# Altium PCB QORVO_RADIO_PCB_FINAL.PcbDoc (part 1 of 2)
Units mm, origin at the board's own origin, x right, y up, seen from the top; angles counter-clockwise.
Board outline 125 x 75 mm, 6 copper layers (Top Layer (RF), Int1 (GND), Int2 (5V+3.3V), Int3 (Controls), Int4 (GND), Bottom Layer (RF)), stack 1.538 mm thick; 307 components, 160 nets, 820 pads, 887 vias.
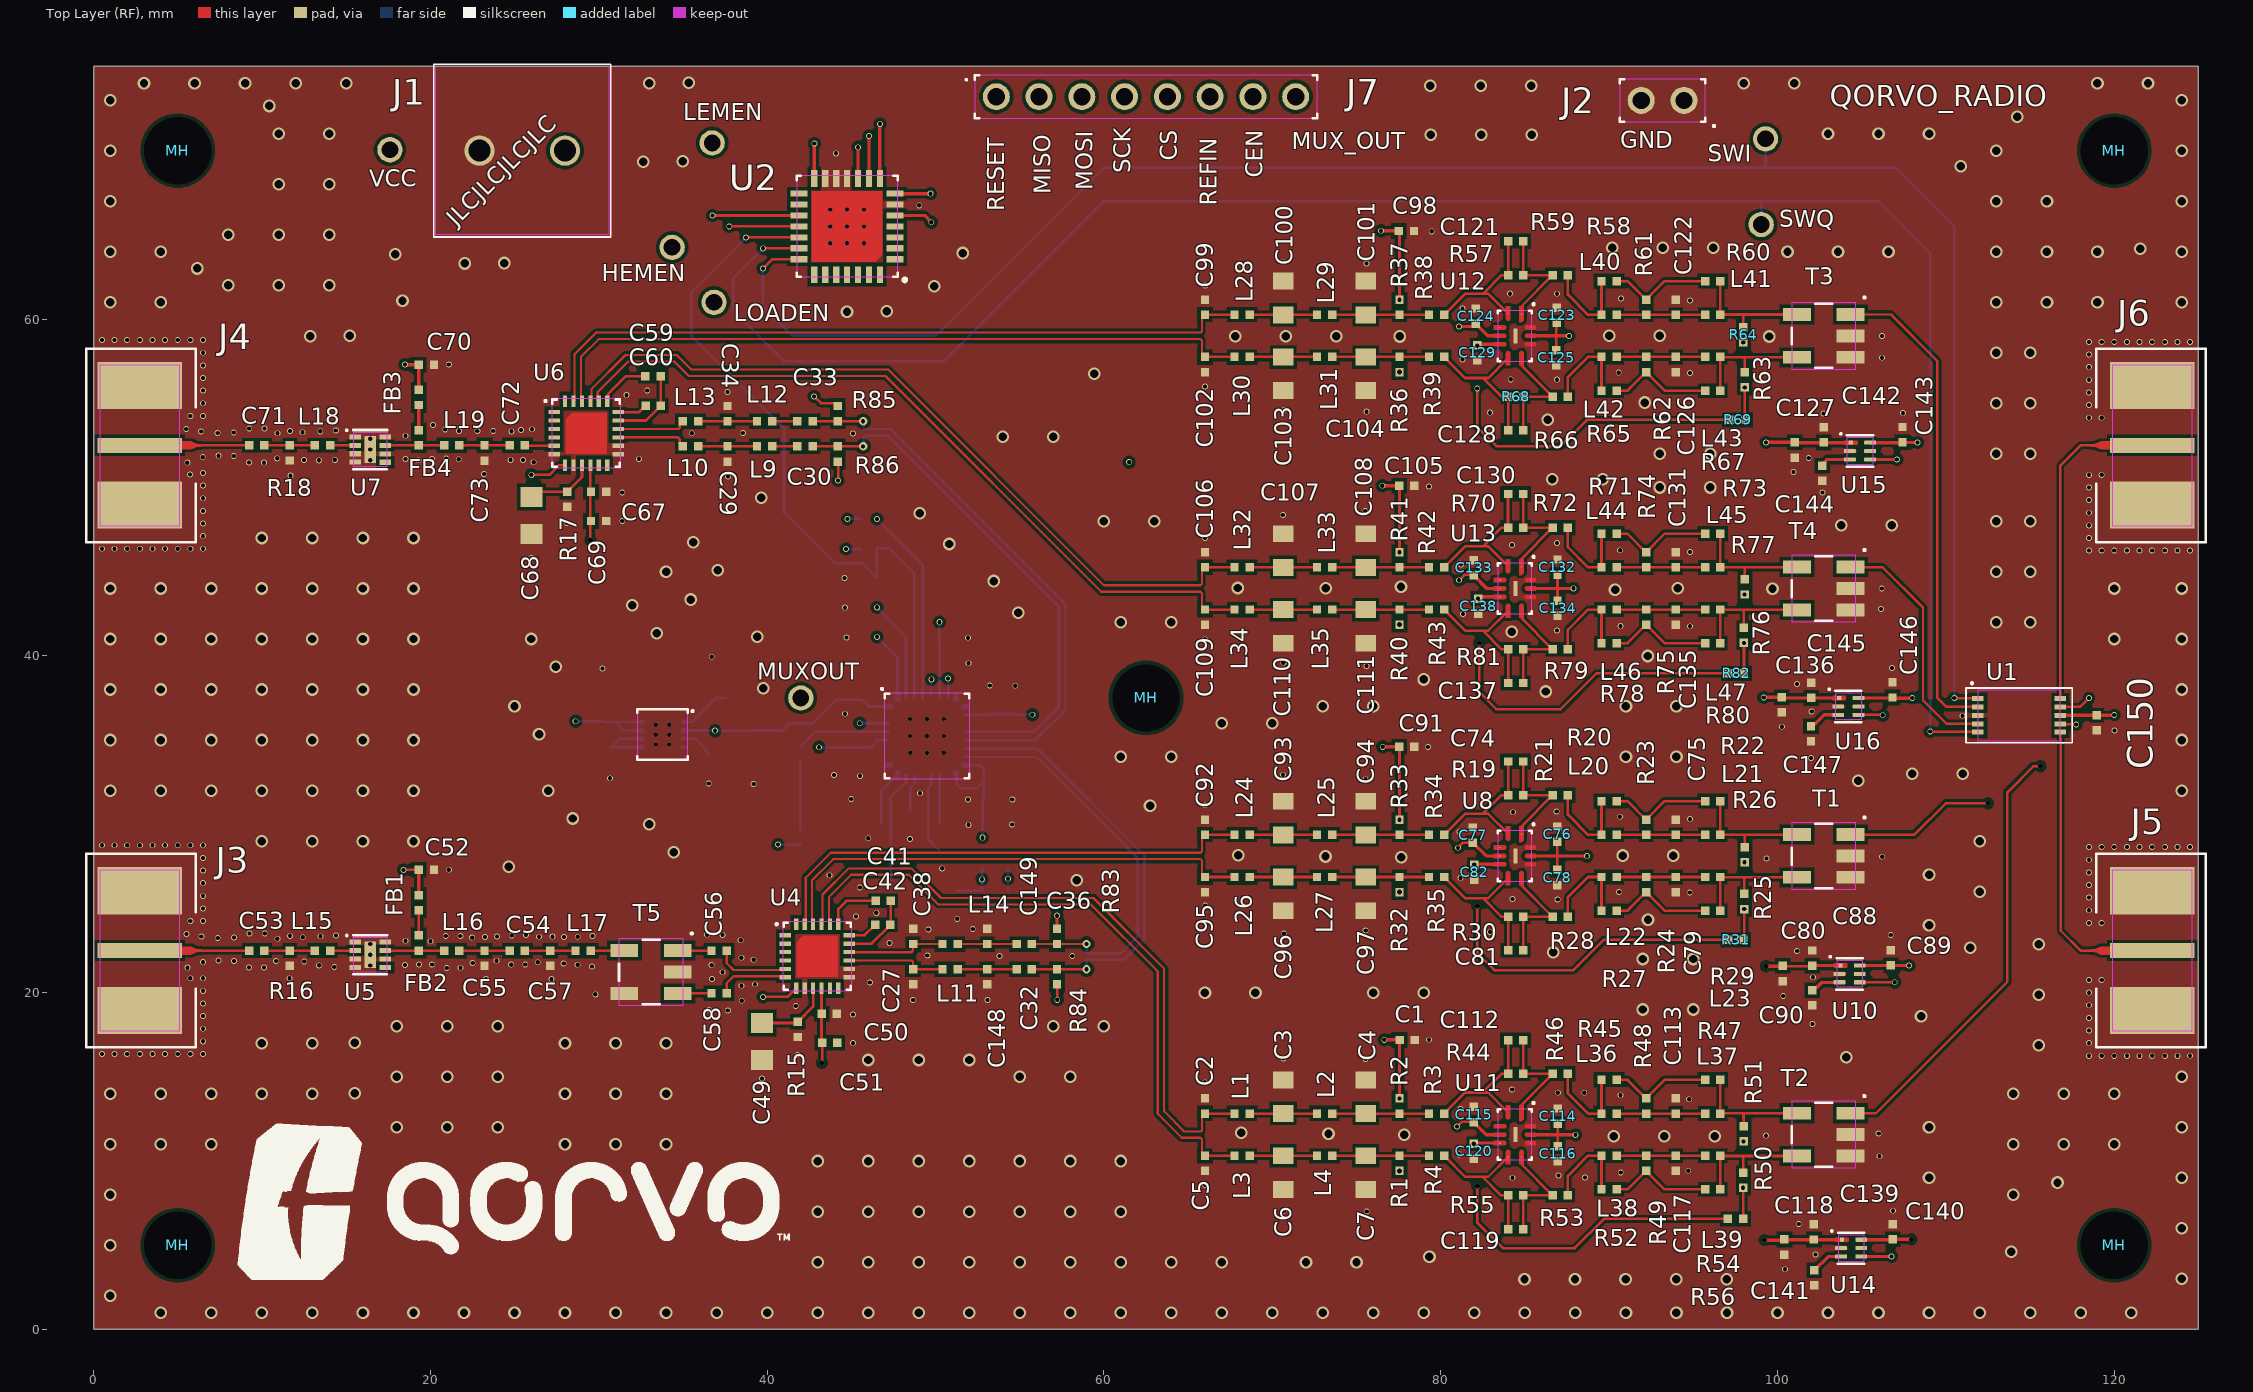
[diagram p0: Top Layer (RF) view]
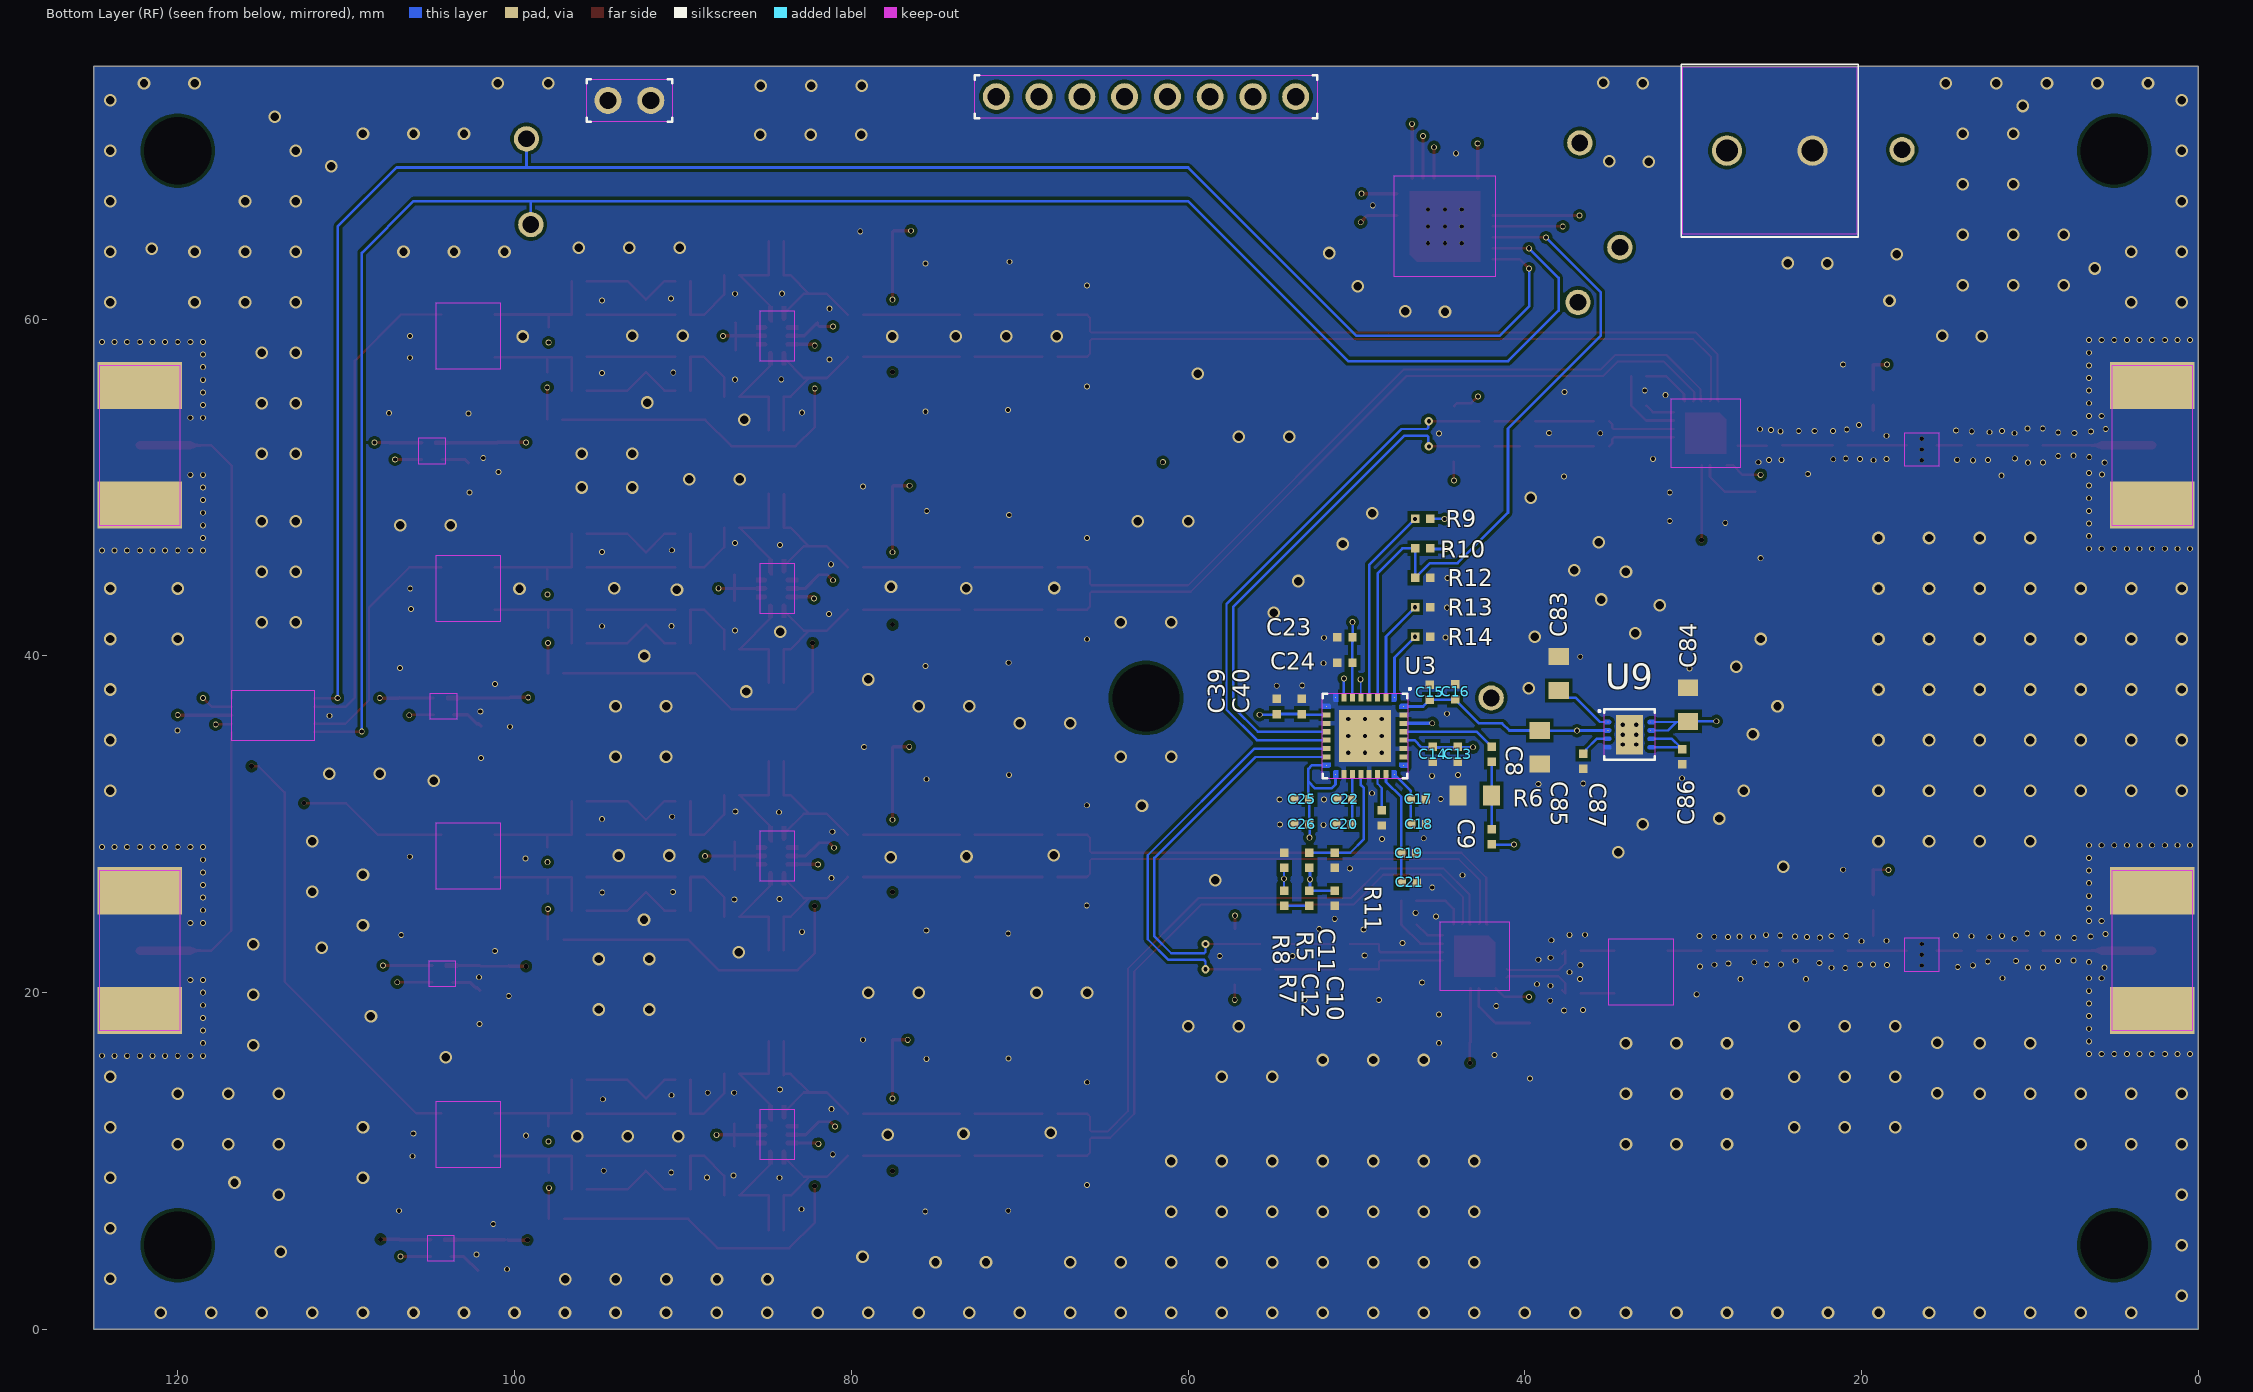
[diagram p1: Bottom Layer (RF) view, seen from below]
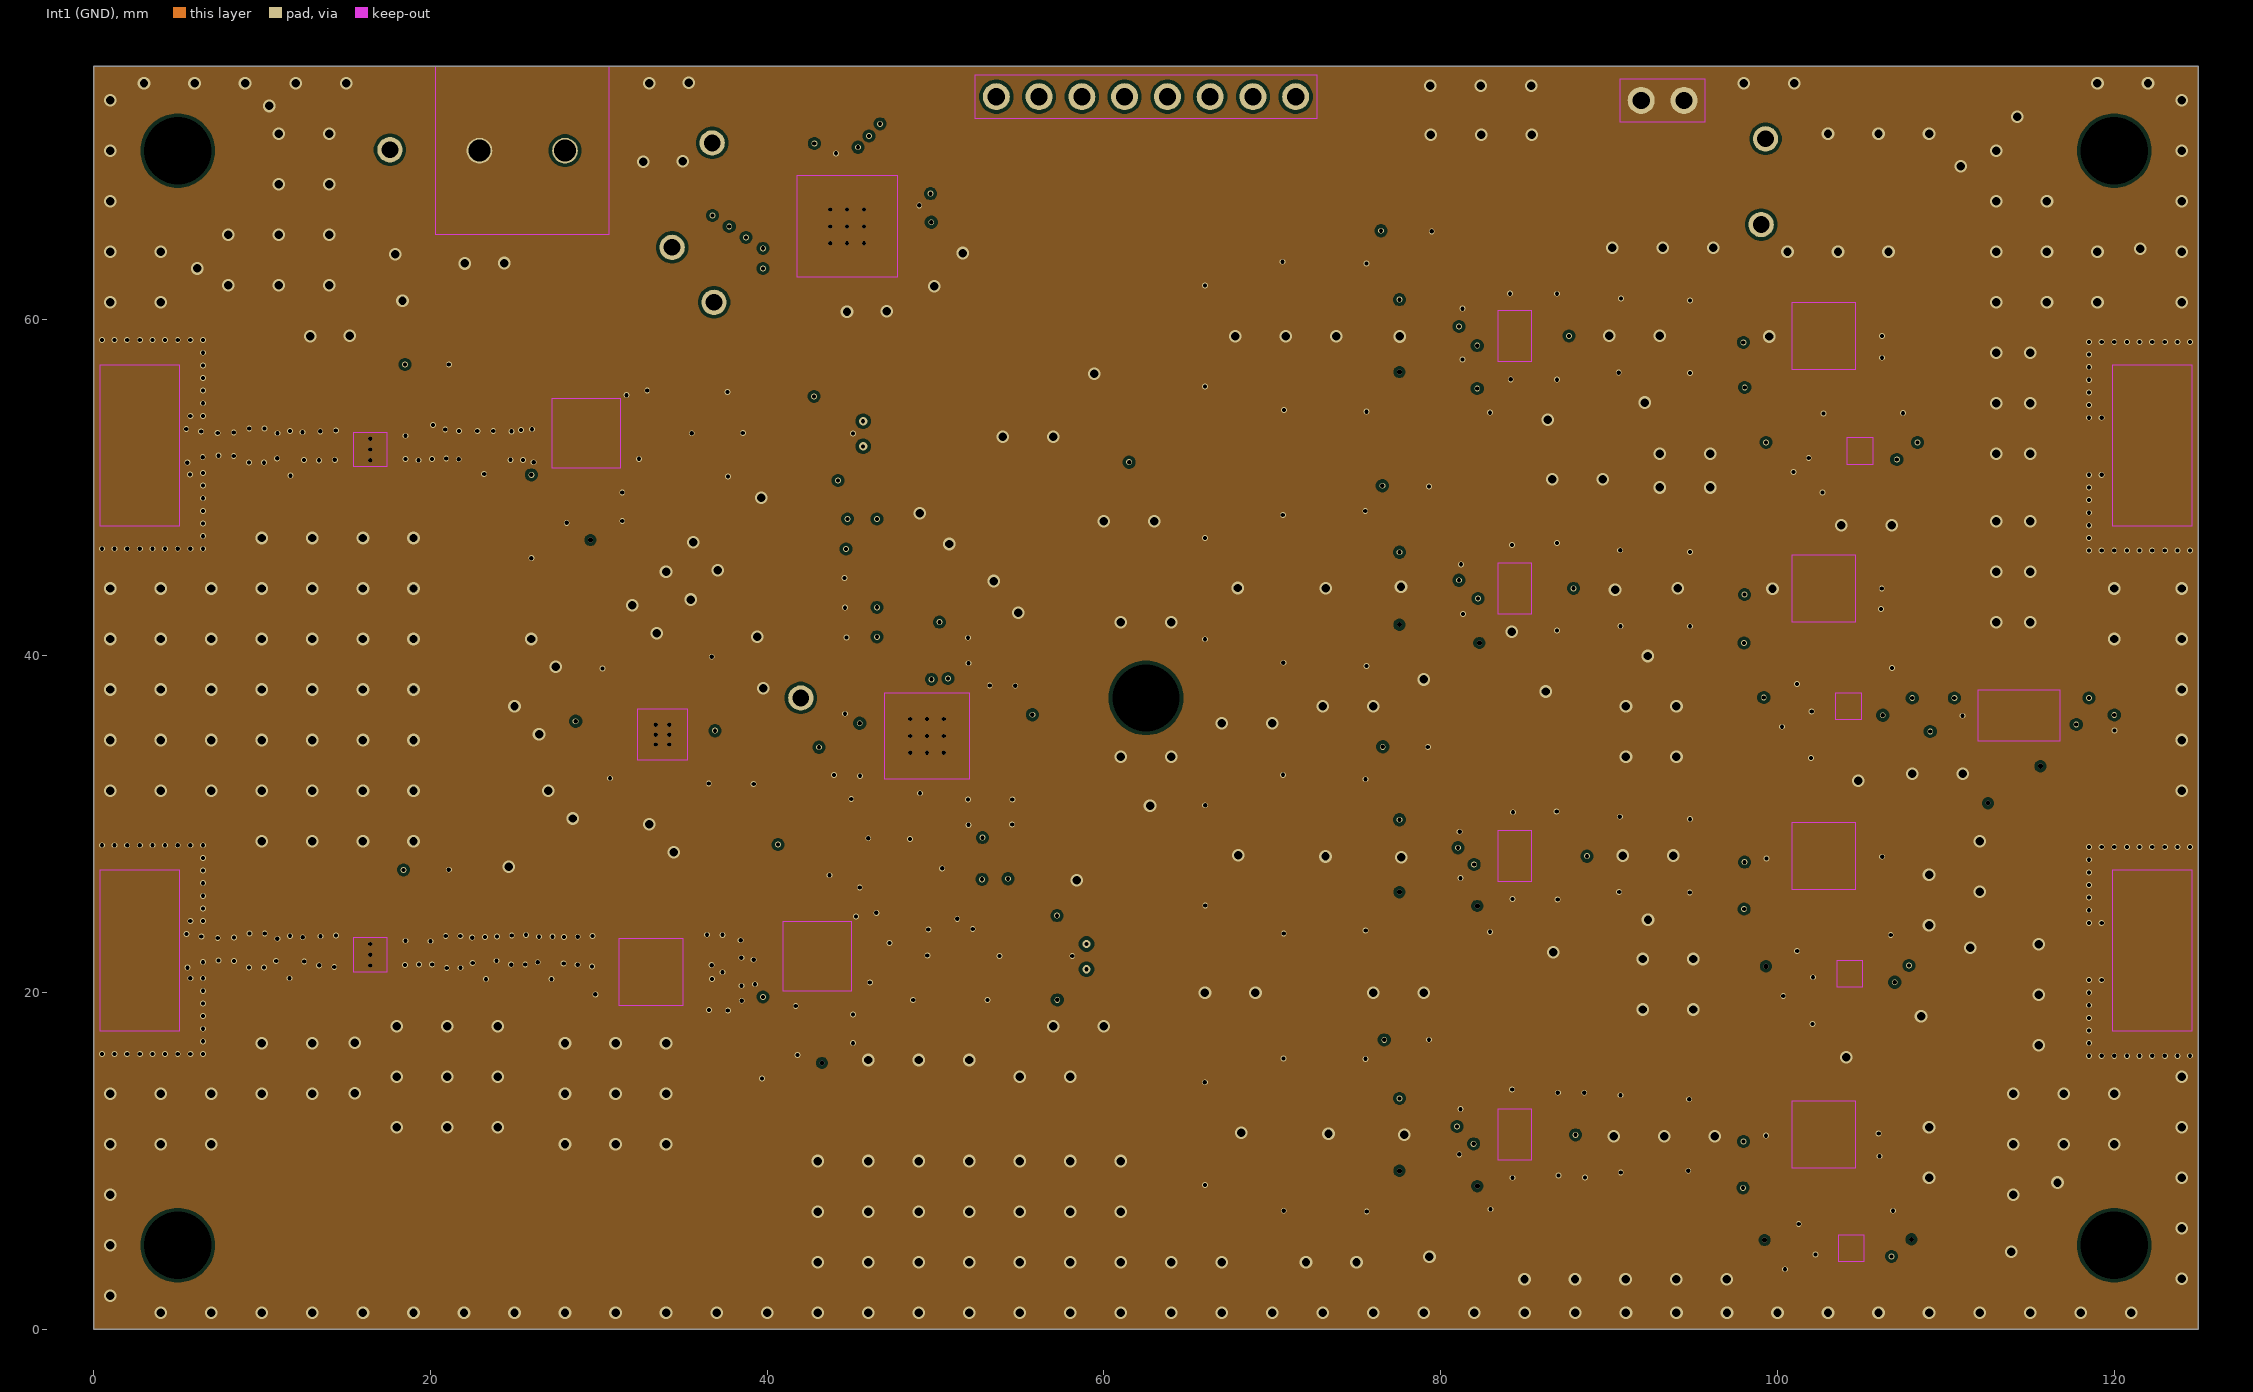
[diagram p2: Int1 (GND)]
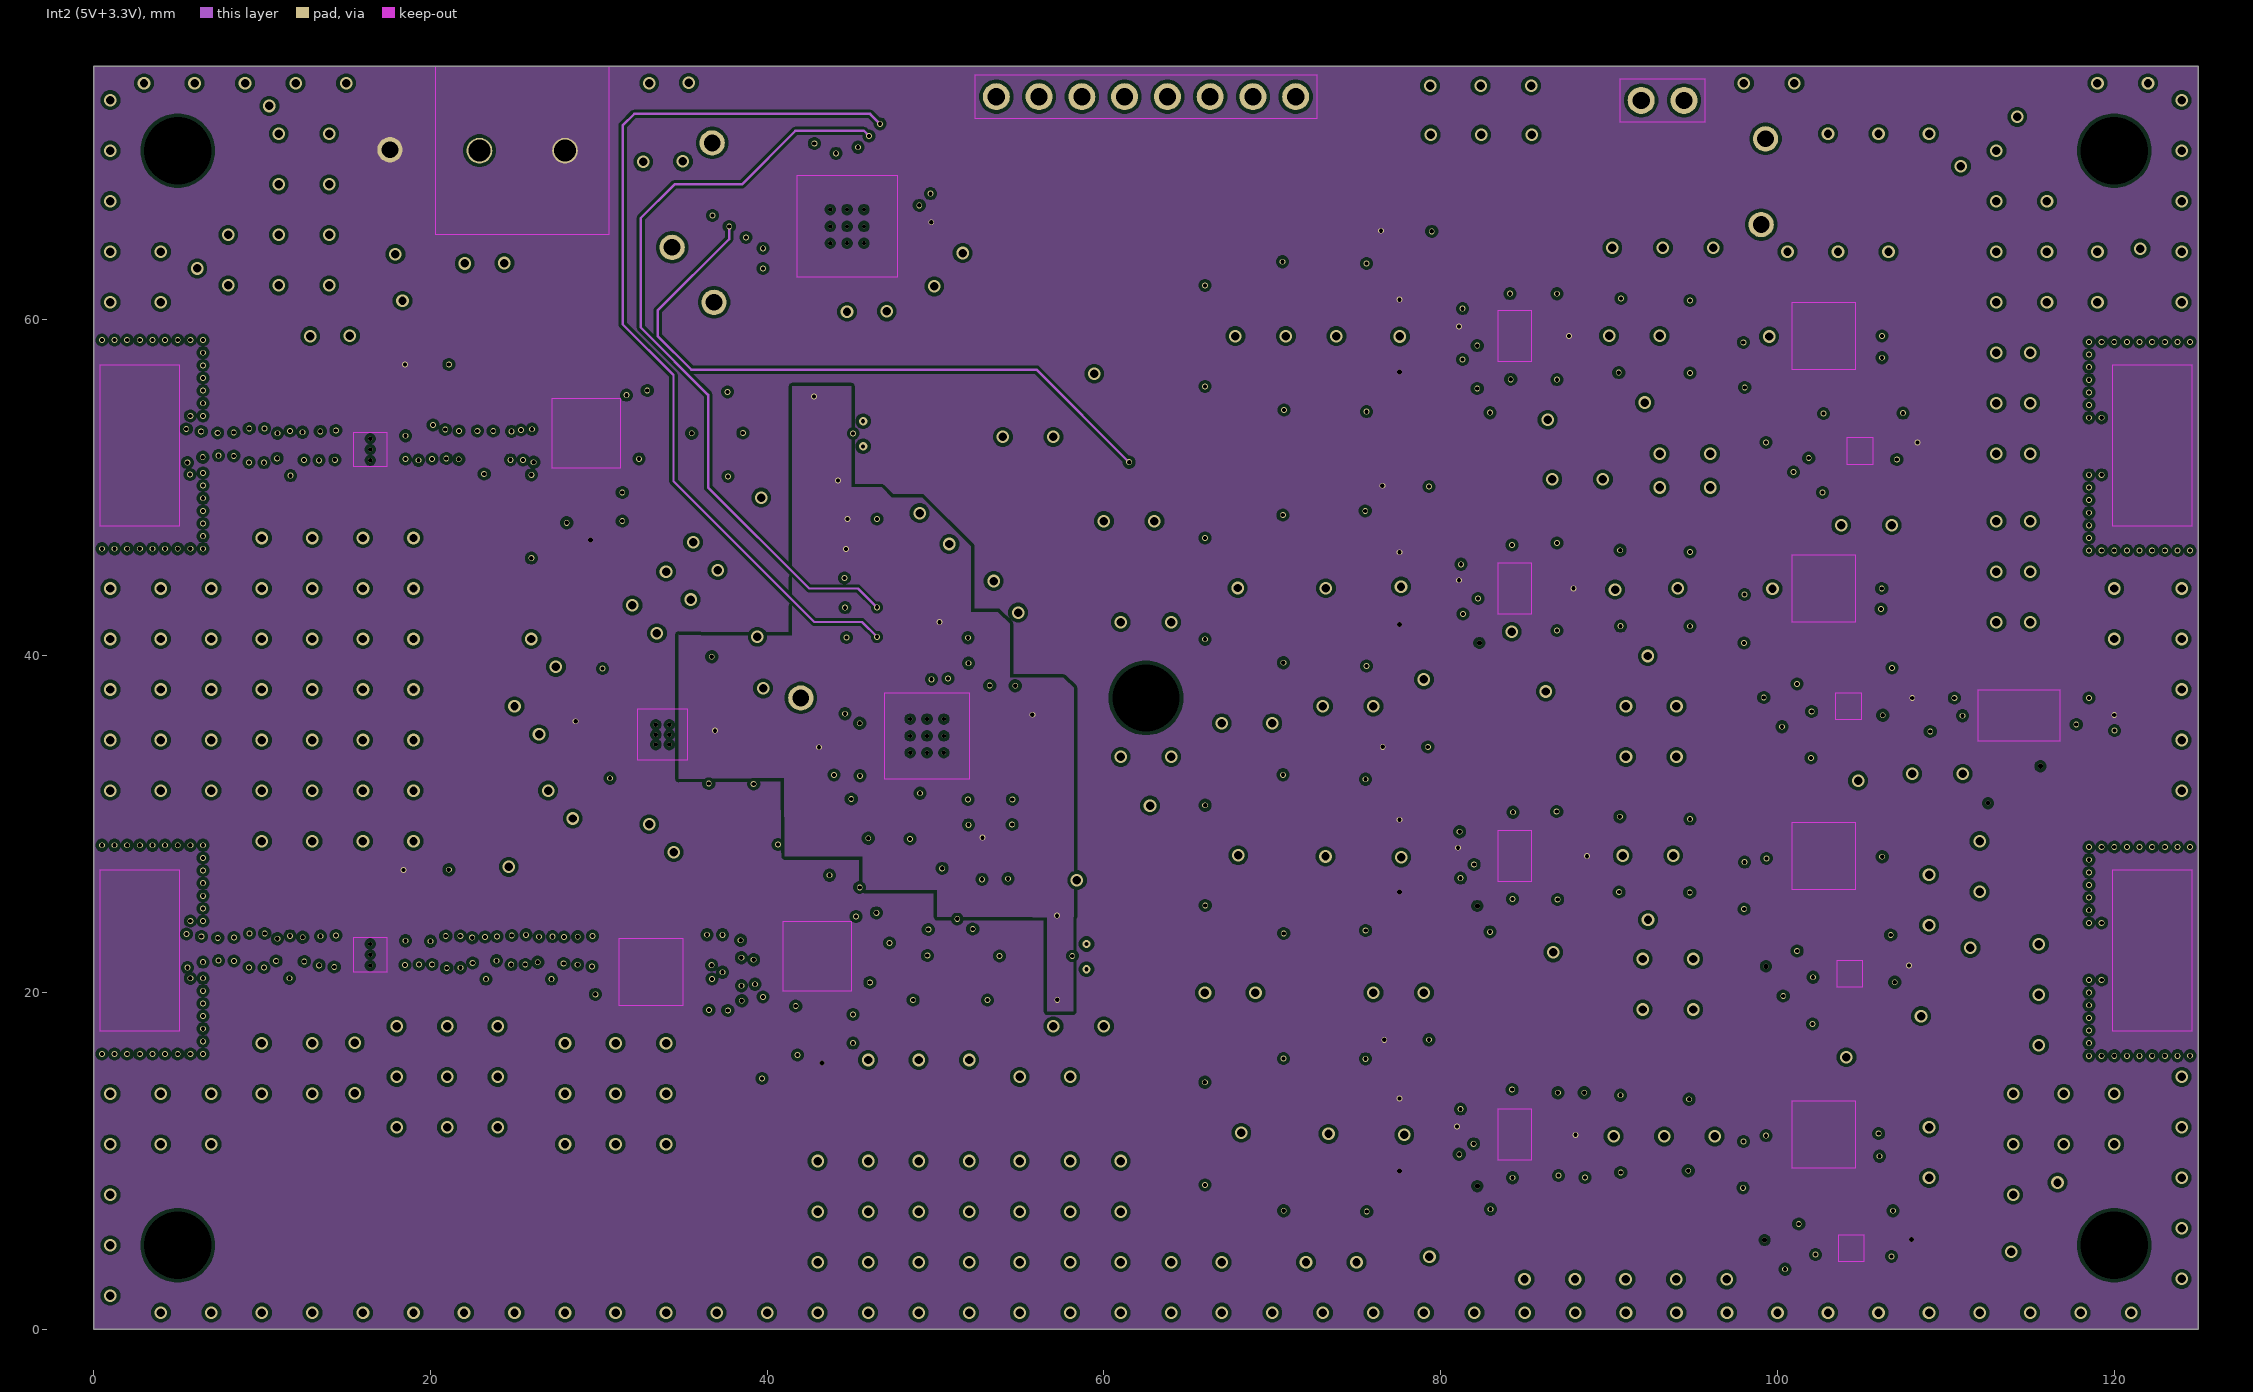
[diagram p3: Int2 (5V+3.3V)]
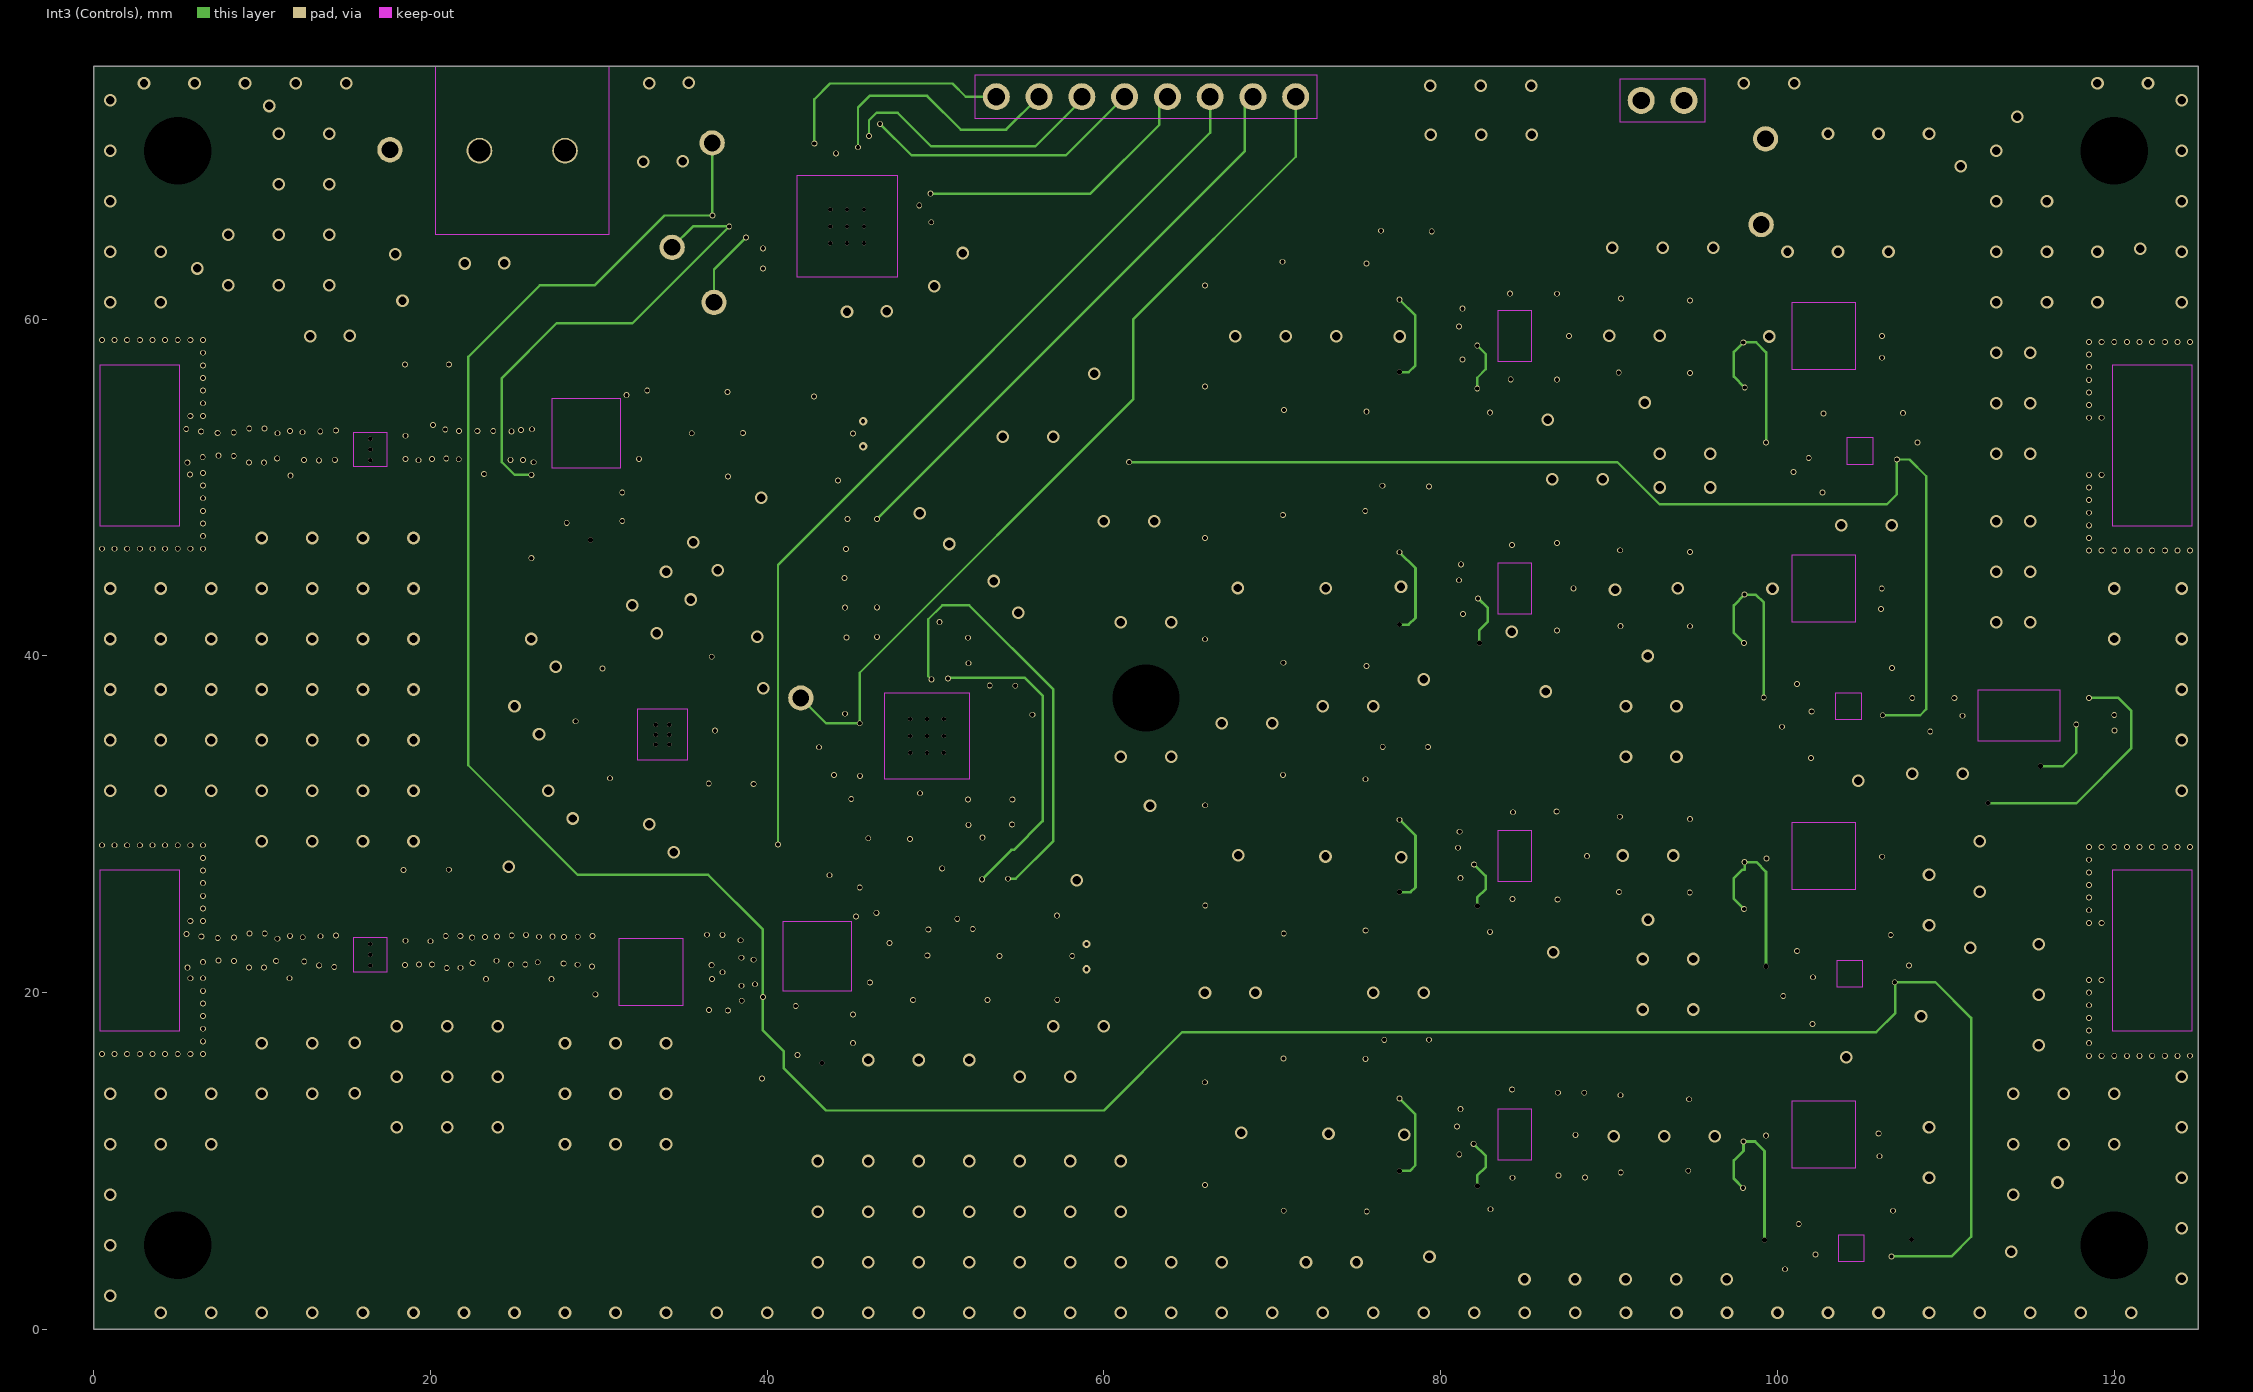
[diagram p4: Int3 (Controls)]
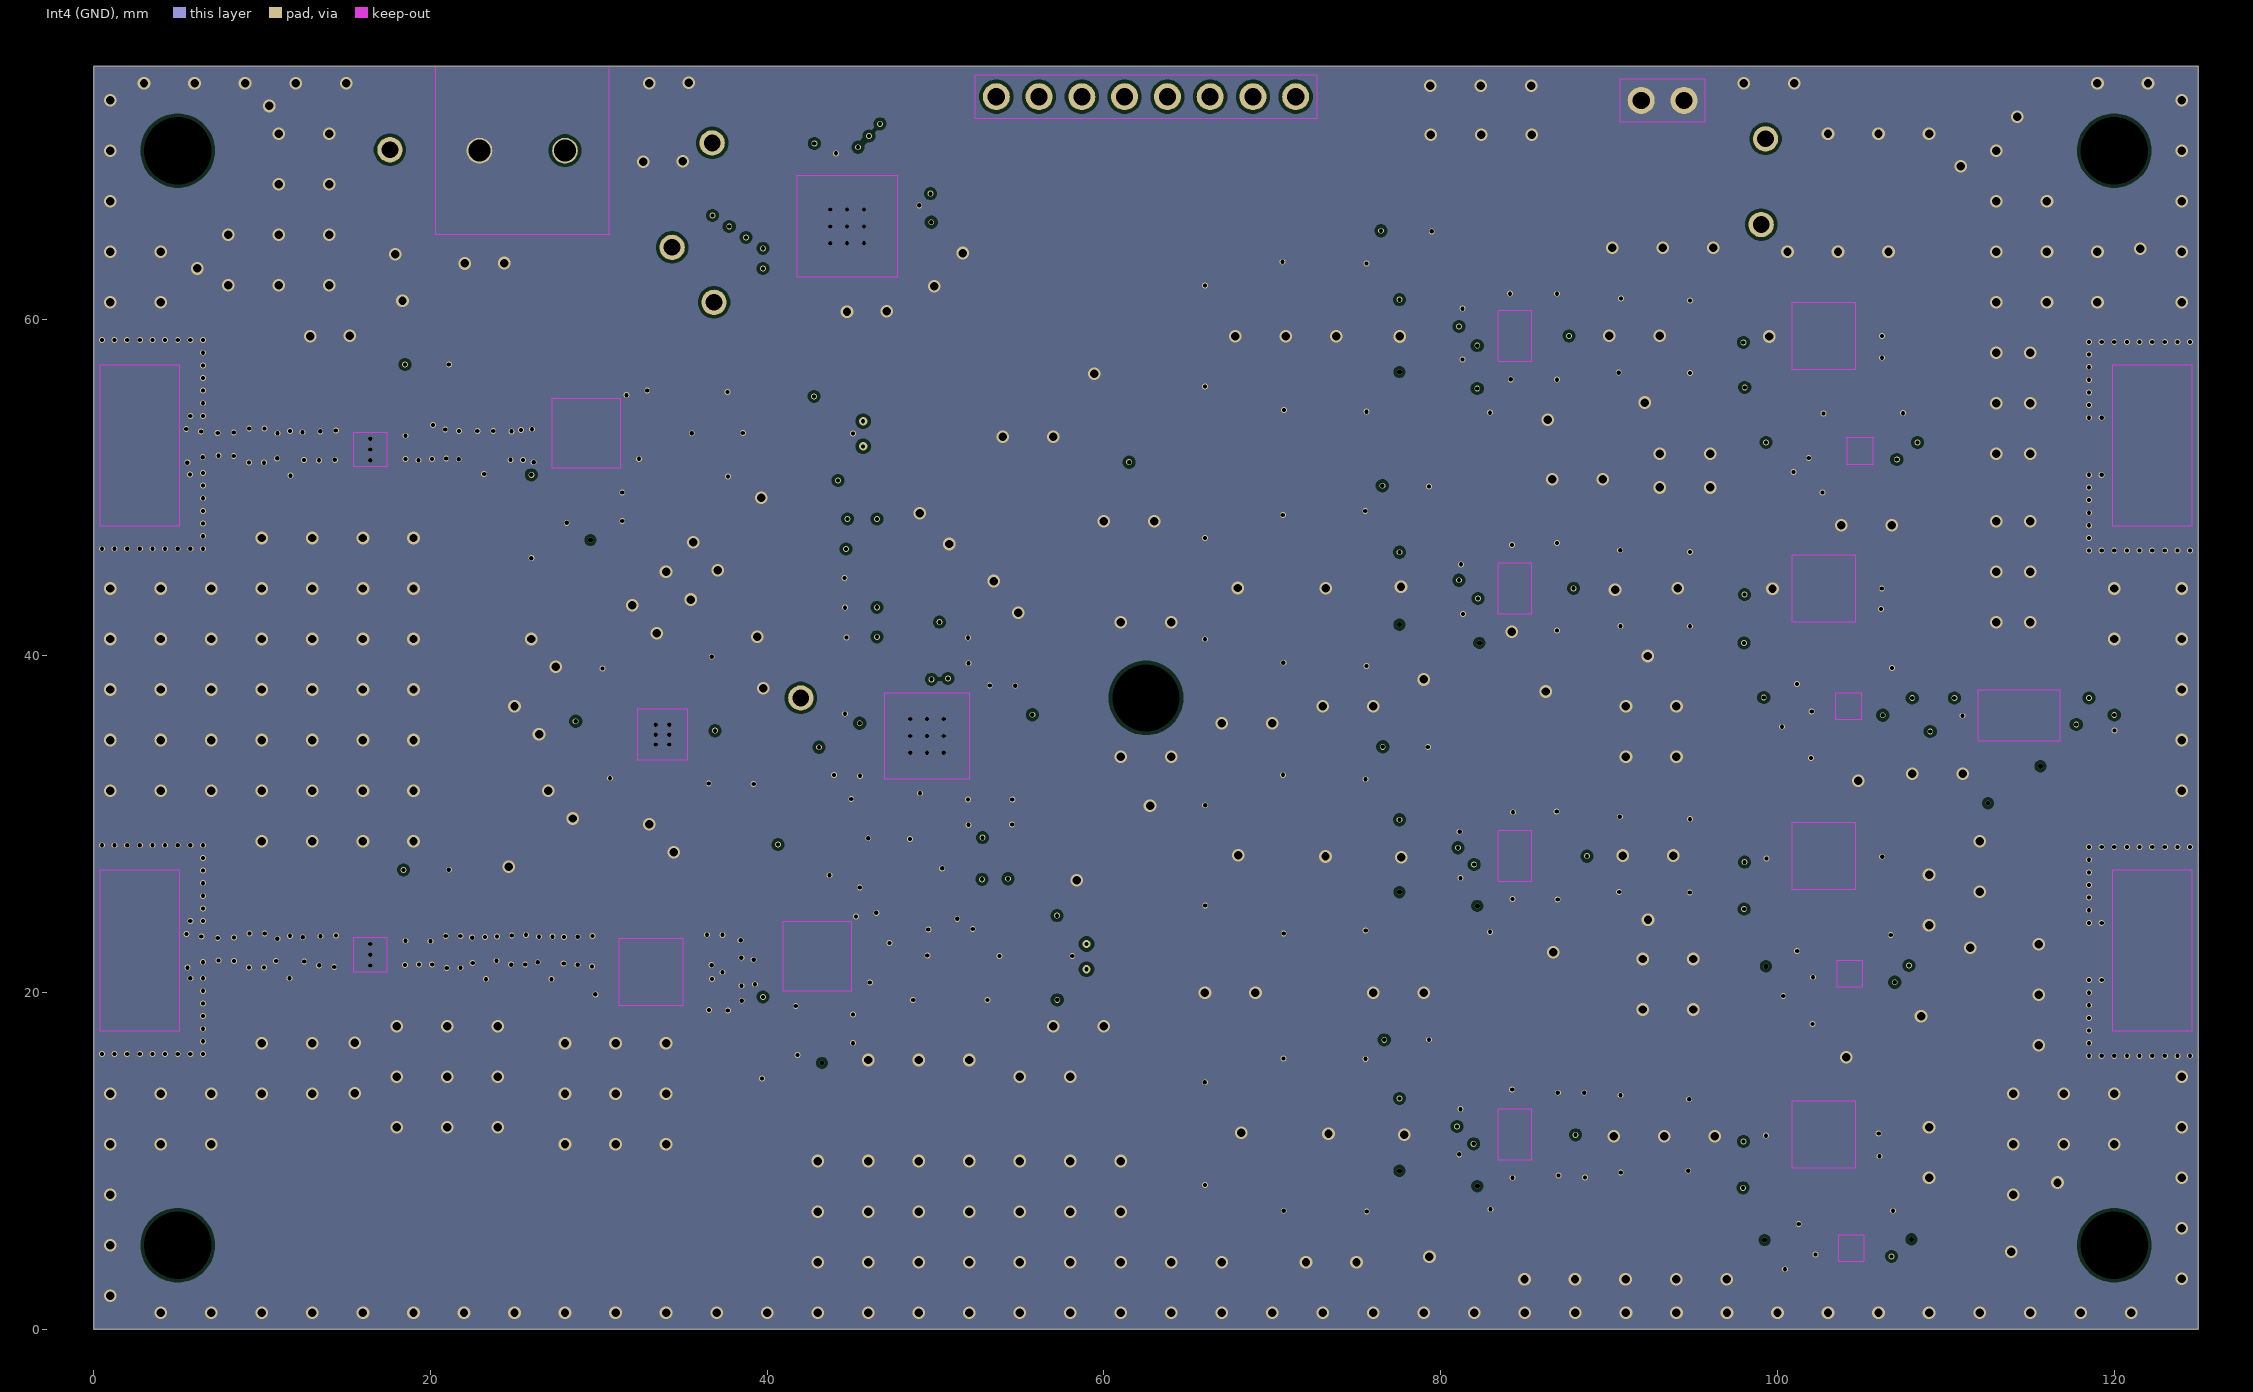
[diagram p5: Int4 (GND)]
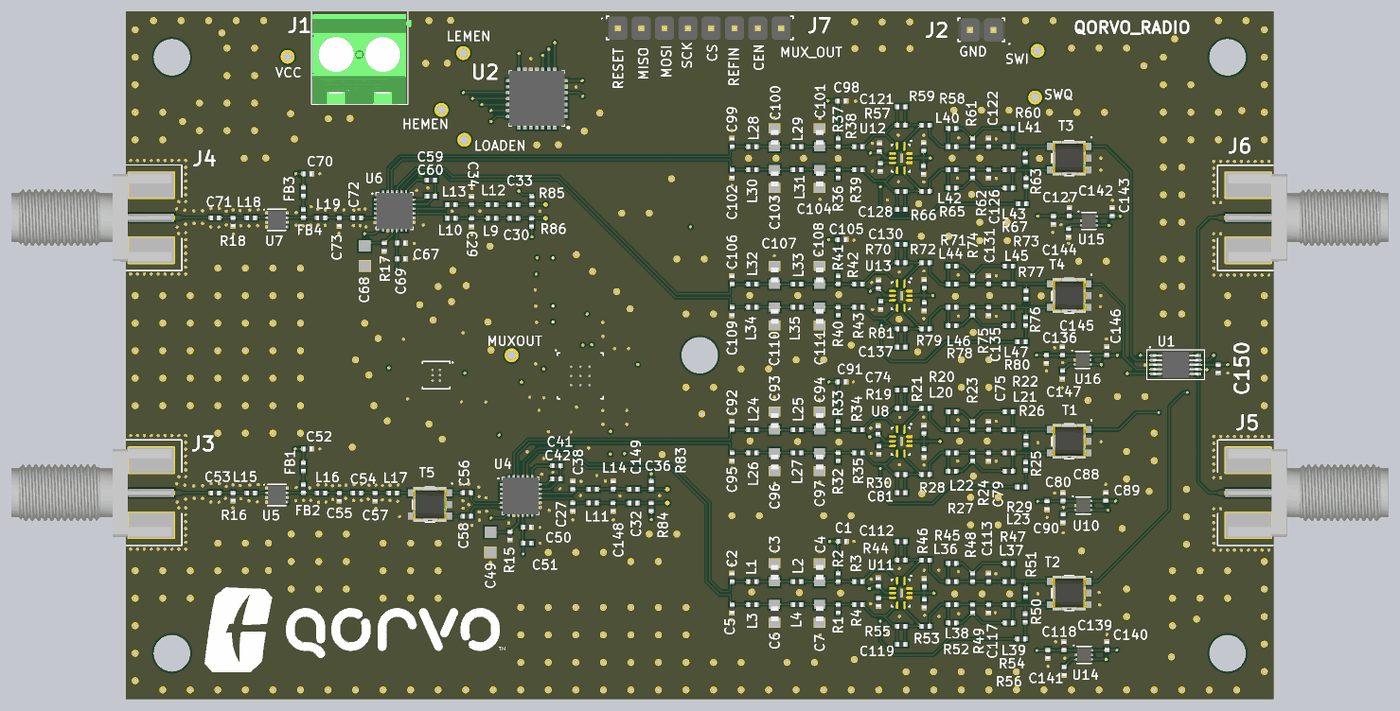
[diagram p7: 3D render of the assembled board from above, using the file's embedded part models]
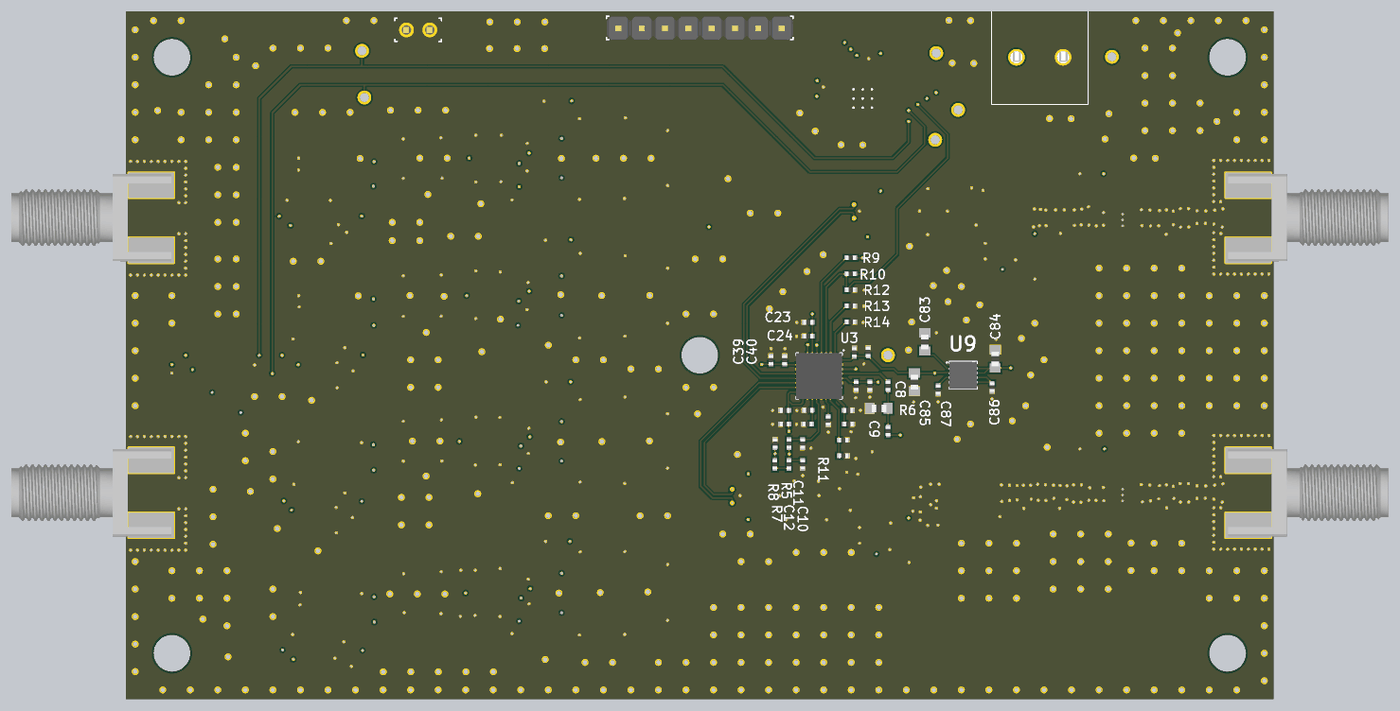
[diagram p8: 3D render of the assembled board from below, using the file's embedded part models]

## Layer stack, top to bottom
Top Solder: solder mask 0.0254, SM-001, Dk 3.8
Top Layer (RF): signal copper 0.035
Dielectric 1: prepreg 0.0994, PP-015, Dk 4.1
Int1 (GND): signal copper 0.0152
Dielectric 3: core 0.55, Core-035, Dk 4.6
Int2 (5V+3.3V): signal copper 0.0152
Dielectric 4: prepreg 0.1088, PP-016, Dk 4.16
Int3 (Controls): signal copper 0.0152
Dielectric 6: core 0.55, Core-035, Dk 4.6
Int4 (GND): signal copper 0.0152
Dielectric 8: prepreg 0.0994, PP-015, Dk 4.1
Bottom Layer (RF): signal copper 0.035
Bottom Solder: solder mask 0.0254, SM-001, Dk 3.8

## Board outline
0,75 125,75 125,0 0,0

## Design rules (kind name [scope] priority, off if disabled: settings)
Clearance [All] p1: gap=0.2 ignorepadtopadclearanceinfootprint=FALSE except(0.15: Arc-SMDPad Track-SMDPad SMDPad-SMDPad; 0.165: Arc-Fill Arc-Poly Arc-Region Track-Fill Track-Poly Track-Region; 0.28: Arc-THPad Track-THPad)
Clearance FILTER_C [InNetClass('R50') vs InNet('GND')] p2: gap=0.2 ignorepadtopadclearanceinfootprint=FALSE except(0.1: Arc-Arc Arc-Track Arc-SMDPad Track-Track Track-SMDPad; 0.15: SMDPad-SMDPad; 0.165: Arc-Fill Arc-Poly Arc-Region Track-Fill Track-Poly Track-Region; 0.28: Arc-THPad Track-THPad)
Clearance RF50_C [InNetClass('RF50') vs InNet('GND')] p3: gap=0.2 ignorepadtopadclearanceinfootprint=FALSE except(0.1: Arc-Arc Arc-Track Arc-SMDPad Track-Track Track-SMDPad; 0.15: SMDPad-SMDPad; 0.165: Arc-Fill Arc-Poly Arc-Region Track-Fill Track-Poly Track-Region; 0.28: Arc-THPad Track-THPad)
DiffPairsRouting D100 [InDifferentialPairClass('DIFF100')] p1: maxlimit=0.25 minlimit=0.127 mostfreqgap=0.127 toplayer_mingap=0.25 toplayer_prefgap=0.25 toplayer_minwidth=0.128 toplayer_maxwidth=0.143 toplayer_prefwidth=0.128 midlayer1_maxgap=0.127 midlayer1_minwidth=0.078 midlayer1_maxwidth=0.078 midlayer1_prefwidth=0.078 midlayer2_maxgap=0.127 midlayer2_minwidth=0.078 midlayer2_maxwidth=0.078 midlayer2_prefwidth=0.078 midlayer3_maxgap=0.127 midlayer3_minwidth=0.076 midlayer3_maxwidth=0.076 midlayer3_prefwidth=0.076 midlayer4_maxgap=0.127 midlayer4_minwidth=0.076 midlayer4_maxwidth=0.076 midlayer4_prefwidth=0.076 bottomlayer_mingap=0.25 bottomlayer_prefgap=0.25 bottomlayer_minwidth=0.128 bottomlayer_maxwidth=0.143 bottomlayer_prefwidth=0.128 impedanceprofiledriven=TRUE impedanceprofileid={F19E9E21-5C10-4974-9395-8295DC43AF55} impedanceprofilevalue=100.000000 maxuncoupledlength=12.7
DiffPairsRouting DC100(DC100) [InDifferentialPairClass('RFDIFF100')] p2: maxlimit=0.25 minlimit=0.127 mostfreqgap=0.127 toplayer_mingap=0.25 toplayer_prefgap=0.25 toplayer_minwidth=0.128 toplayer_maxwidth=0.143 toplayer_prefwidth=0.128 midlayer1_maxgap=0.127 midlayer1_minwidth=0.078 midlayer1_maxwidth=0.078 midlayer1_prefwidth=0.078 midlayer2_maxgap=0.127 midlayer2_minwidth=0.078 midlayer2_maxwidth=0.078 midlayer2_prefwidth=0.078 midlayer3_maxgap=0.127 midlayer3_minwidth=0.076 midlayer3_maxwidth=0.076 midlayer3_prefwidth=0.076 midlayer4_maxgap=0.127 midlayer4_minwidth=0.076 midlayer4_maxwidth=0.076 midlayer4_prefwidth=0.076 bottomlayer_mingap=0.25 bottomlayer_prefgap=0.25 bottomlayer_minwidth=0.128 bottomlayer_maxwidth=0.143 bottomlayer_prefwidth=0.128 impedanceprofiledriven=TRUE impedanceprofileid={F19E9E21-5C10-4974-9395-8295DC43AF55} impedanceprofilevalue=100.000000 maxuncoupledlength=12.7
HoleSize [All] p1: absolutevalues=TRUE maxlimit=4.2 minlimit=0.025 maxpercent=80.000 minpercent=20.000
MinimumSolderMaskSliver [All] p1: minsoldermaskwidth=0.09
PolygonConnect [All] p1: connectstyle=Direct reliefconductorwidth=0.254 reliefentries=4 polygonreliefangle="90 Angle" airgapwidth=0.254
RoutingVias [All] p1: holewidth=0.2 width=0.3 viastyle="Through Hole" minholewidth=0.15 minwidth=0.25 maxholewidth=0.3 maxwidth=0.5
SilkToSilkClearance [All] p1: silktosilkclearance=0.1
SilkToSolderMaskClearance [IsPad] p1: minsilkscreentomaskgap=0.15 clearancetoexposedcopper=TRUE
SolderMaskExpansion [All] p1: expansion=0 istentingtop=FALSE
SupplyNets "Schematic Supply Nets" [InNet('GND')] p1: voltage=0.000
UnRoutedNet [All] p1: checkbadconnections=TRUE
Width FILTER_W [InNetClass('R50')] p1: maxlimit=0.8 minlimit=0.1 preferedwidth=0.142 toplayer_prefwidth=0.143 midlayer1_minwidth=0.142 midlayer1_maxwidth=0.142 midlayer2_minwidth=0.142 midlayer2_maxwidth=0.142 midlayer3_minwidth=0.111 midlayer3_maxwidth=0.111 midlayer3_prefwidth=0.111 midlayer4_minwidth=0.111 midlayer4_maxwidth=0.111 midlayer4_prefwidth=0.111 bottomlayer_prefwidth=0.143 impedanceprofiledriven=TRUE impedanceprofileid={DEF68B85-ACDE-4DF0-B51A-E7C985F0C7FE} impedanceprofilevalue=50.000000 minimp=50.000000 maximp=50.000000 favimp=50.000000
Width RF50_W [InNetClass('RF50')] p2: maxlimit=0.8 minlimit=0.111 preferedwidth=0.118 toplayer_minwidth=0.14 toplayer_prefwidth=0.143 midlayer1_minwidth=0.118 midlayer1_maxwidth=0.118 midlayer2_minwidth=0.118 midlayer2_maxwidth=0.118 midlayer3_maxwidth=0.111 midlayer3_prefwidth=0.111 midlayer4_maxwidth=0.111 midlayer4_prefwidth=0.111 bottomlayer_minwidth=0.14 bottomlayer_maxwidth=0.2 bottomlayer_prefwidth=0.143 impedanceprofiledriven=TRUE impedanceprofileid={1DB529B2-8079-41E9-A1C0-D2A62ED68116} impedanceprofilevalue=50.000000 minimp=50.000000 maximp=50.000000 favimp=50.000000
Width CONTROLS [InNetClass('CONTROLS')] p3: maxlimit=0.3 minlimit=0.128 preferedwidth=0.142 toplayer_minwidth=0.15 toplayer_prefwidth=0.157 midlayer1_minwidth=0.142 midlayer1_maxwidth=0.142 midlayer2_minwidth=0.142 midlayer2_maxwidth=0.142 midlayer3_maxwidth=0.128 midlayer3_prefwidth=0.128 midlayer4_maxwidth=0.128 midlayer4_prefwidth=0.128 bottomlayer_minwidth=0.15 bottomlayer_prefwidth=0.157 impedanceprofiledriven=TRUE impedanceprofileid={B8A1BD53-F7C3-4A7C-B618-B5A62868B429} impedanceprofilevalue=50.000000 minimp=50.000000 maximp=50.000000 favimp=50.000000
24 further rules are at their usual default settings.

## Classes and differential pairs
net class POWER: AVDD NetC83_1 NetC86_2 NetC87_2 VCC
net class CONTROLS: CS "HEM EN" I/O_I I/O_Q "LEM EN" LOAD_EN MISO MOSI MUX_OUT REFIN RESET SCK
differential pair class RFDIFF100: "LE_LNA OUTPUT" LO_12 LO_14 LO_HE_OUT LO_LE_OUT
differential pair class DIFF100: I_HE_LPF_INPUT I_HE_LPF_OUTPUT I_LE_LPF_INPUT I_LE_LPF_OUTPUT Q_HE_LPF_INPUT Q_HE_LPF_OUTPUT Q_LE_LPF_INPUT Q_LE_LPF_OUTPUT
net class R50: CHIP_EN CPOUT "I HE CH" "I LE CH" NetC3_1 NetC4_1 NetC6_2 NetC7_2 NetC8_1 NetC8_2 NetC74_2 NetC75_1 NetC79_2 NetC81_2 NetC93_1 NetC94_1 NetC96_2 NetC97_2 NetC100_1 NetC101_1 NetC103_2 NetC104_2 NetC107_1 NetC108_1 NetC110_2 NetC111_2 NetC112_2 NetC113_1 NetC117_2 NetC119_2 NetC121_2 NetC122_1 NetC126_2 NetC128_2 NetC130_2 NetC131_1 NetC135_2 NetC137_2 NetJ5_6 NetJ6_6 NetL20_1 NetL22_1 NetL36_1 NetL38_1 NetL40_1 NetL42_1 NetL44_1 NetL46_1 NetR20_2 NetR24_1 NetR45_2 NetR49_1 NetR58_2 NetR62_1 NetR71_2 NetR75_1 "Q HE CH" "Q LE CH" REFIN SW VTUNE
net class RF50: "HE LNA OUTPUT" LEL-10 NetC29_1 NetC30_2 NetC32_1 NetC33_2 NetC34_2 NetC36_1 NetC53_1 NetC53_2 NetC54_1 NetC56_2 NetC58_1 NetC71_1 NetC71_2 NetC72_1 NetFB2_1 NetFB4_1 NetL15_2 NetL17_2 NetL18_2
component class "U_0.9V REG_4": C145 C146 C147 U16
component class "U_0.9V REG_3": C142 C143 C144 U15
component class "U_0.9V REG_2": C139 C140 C141 U14
component class "U_0.9V REG_1": C88 C89 C90 U10
component class U_SWITCH: C150 U1
component class "U_Q LE LPF": C1 C2 C3 C4 C5 C6 C7 L1 L2 L3 L4 R1 R2 R3 R4
component class "U_Q LE AA": C112 C113 C114 C115 C116 C117 C118 C119 C120 L36 L37 L38 L39 R44 R45 R46 R47 R48 R49 R50 R51 R52 R53 R54 R55 R56 T2 U11
component class "U_Q HE LPF": C105 C106 C107 C108 C109 C110 C111 L32 L33 L34 L35 R40 R41 R42 R43
component class "U_Q HE AA": C130 C131 C132 C133 C134 C135 C136 C137 C138 L44 L45 L46 L47 R70 R71 R72 R73 R74 R75 R76 R77 R78 R79 R80 R81 R82 T4 U13
component class U_LO: C8 C9 C10 C11 C12 C13 C14 C15 C16 C17 C18 C19 C20 C21 C22 C23 C24 C25 C26 C27 C29 C30 C32 C33 C34 C36 C38 C39 C40 C148 C149 L9 L10 L11 L12 L13 L14 R5 R6 R7 R8 R9 R10 R11 R12 R13 R14 R83 R84 R85 R86 TEST? U3
component class "U_LE Mixer": C41 C42 C49 C50 C51 R15 U4
component class "U_LE LNA": C52 C53 C54 C55 C56 C57 C58 FB1 FB2 L15 L16 L17 R16 T5 U5
component class "U_I LE LPF": C91 C92 C93 C94 C95 C96 C97 L24 L25 L26 L27 R32 R33 R34 R35
component class "U_I LE AA": C74 C75 C76 C77 C78 C79 C80 C81 C82 L20 L21 L22 L23 R19 R20 R21 R22 R23 R24 R25 R26 R27 R28 R29 R30 R31 T1 U8
component class "U_I HE LPF": C98 C99 C100 C101 C102 C103 C104 L28 L29 L30 L31 R36 R37 R38 R39
component class "U_I HE AA": C121 C122 C123 C124 C125 C126 C127 C128 C129 L40 L41 L42 L43 R57 R58 R59 R60 R61 R62 R63 R64 R65 R66 R67 R68 R69 T3 U12
component class "U_HE Mixer": C59 C60 C67 C68 C69 R17 U6
component class "U_HE LNA": C70 C71 C72 C73 FB3 FB4 L18 L19 R18 U7
component class "U_3.3v REG": C83 C84 C85 C86 C87 U9
component class SYSTEM: HEMEN J1 J2 J3 J4 J5 J6 J7 LEMEN LOADEN MUXOUT SWI SWQ U2 VCC
differential pair LO_14: +LO_14_P -LO_14_N
differential pair LO_12: +LO_12_P -LO_12_N
differential pair Q_LE_LPF_OUTPUT: +Q_LE_LPF_OUTPUT_P -Q_LE_LPF_OUTPUT_N
differential pair Q_LE_LPF_INPUT: +Q_LE_LPF_INPUT_P -Q_LE_LPF_INPUT_N
differential pair Q_HE_LPF_OUTPUT: +Q_HE_LPF_OUTPUT_P -Q_HE_LPF_OUTPUT_N
differential pair Q_HE_LPF_INPUT: +Q_HE_LPF_INPUT_P -Q_HE_LPF_INPUT_N
differential pair LO_LE_OUT: +LO_LE_OUT_P -LO_LE_OUT_N
differential pair LO_HE_OUT: +LO_HE_OUT_P -LO_HE_OUT_N
differential pair "LE_LNA OUTPUT": +"LE_LNA OUTPUT_P" -"LE_LNA OUTPUT_N"
differential pair I_LE_LPF_OUTPUT: +I_LE_LPF_OUTPUT_P -I_LE_LPF_OUTPUT_N
differential pair I_LE_LPF_INPUT: +I_LE_LPF_INPUT_P -I_LE_LPF_INPUT_N
differential pair I_HE_LPF_OUTPUT: +I_HE_LPF_OUTPUT_P -I_HE_LPF_OUTPUT_N
differential pair I_HE_LPF_INPUT: +I_HE_LPF_INPUT_P -I_HE_LPF_INPUT_N

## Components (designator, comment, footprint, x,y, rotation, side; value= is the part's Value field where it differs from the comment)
C1 "GRM155R61H105KE05D" "0402 CAP_IND_RES" 78.008,17.186 r180 top
C2 "GJM1555C1H470FB01D" "0402 CAP_IND_RES" 66.003,13.269 r90 top
C3 "CC0603JRNPO9BN151" 0603_CAP 70.653,13.819 r90 top
C4 "CC0603JRNPO9BN151" 0603_CAP 75.553,13.819 r90 top
C5 "GJM1555C1H470FB01D" "0402 CAP_IND_RES" 66.003,9.869 r90 top
C6 "CC0603JRNPO9BN151" 0603_CAP 70.653,9.319 r90 top
C7 "CC0603JRNPO9BN151" 0603_CAP 75.553,9.319 r90 top
C8 "GCM1555C1H102FA16D" "0402 CAP_IND_RES" 41.978,34.159 r270 bottom
C9 "GCM1555C1H102FA16D" "0402 CAP_IND_RES" 41.978,29.259 r270 bottom
C10 "GCM155R71H272KA37D" "0402 CAP_IND_RES" 51.295,25.606 r90 bottom
C11 "GCM1555C1H681JA16D" "0402 CAP_IND_RES" 51.295,27.856 r90 bottom
C12 "GCM1555C1H390JA16D" "0402 CAP_IND_RES" 52.795,25.606 r270 bottom
C13 "CL05B104KO5NNNC" "0402 CAP_IND_RES" 43.978,34.159 r90 bottom
C14 "GJM1555C1H100JB01D" "0402 CAP_IND_RES" 45.478,34.159 r90 bottom
C15 "CL05B104KO5NNNC" "0402 CAP_IND_RES" 45.648,37.836 r270 bottom
C16 "GJM1555C1H100JB01D" "0402 CAP_IND_RES" 44.148,37.857 r270 bottom
C17 "GJM1555C1H100JB01D" "0402 CAP_IND_RES" 46.336,31.493 r180 bottom
C18 "CL05B104KO5NNNC" "0402 CAP_IND_RES" 46.309,29.993 r180 bottom
C19 "GJM1555C1H100JB01D" "0402 CAP_IND_RES" 46.892,28.268 r180 bottom
C20 "GJM1555C1H100JB01D" "0402 CAP_IND_RES" 50.746,29.993 r0 bottom
C21 "CL05B104KO5NNNC" "0402 CAP_IND_RES" 46.875,26.543 r180 bottom
C22 "CL05B104KO5NNNC" "0402 CAP_IND_RES" 50.701,31.493 r0 bottom
C23 "CL05B104KO5NNNC" "0402 CAP_IND_RES" 50.689,41.099 r180 bottom
C24 "GJM1555C1H100JB01D" "0402 CAP_IND_RES" 50.689,39.599 r180 bottom
C25 "GJM1555C1H100JB01D" "0402 CAP_IND_RES" 53.245,31.493 r180 bottom
C26 "CL05B104KO5NNNC" "0402 CAP_IND_RES" 53.245,29.993 r180 bottom
C27 "CQ0402BRNPO9BN2R3" "0402 CAP_IND_RES" 48.667,20.939 r270 top
C29 "GJM1555C1H1R5BB01D" "0402 CAP_IND_RES" 37.65,51.988 r270 top
C30 "GRM1555C1H102JA01D" "0402 CAP_IND_RES" 42.25,52.438 r180 top
C32 "GRM1555C1H102JA01D" "0402 CAP_IND_RES" 55.267,21.389 r0 top
C33 "GRM1555C1H102JA01D" "0402 CAP_IND_RES" 42.25,53.937 r180 top
C34 "GJM1555C1H1R5BB01D" "0402 CAP_IND_RES" 37.65,54.387 r270 top
C36 "GRM1555C1H102JA01D" "0402 CAP_IND_RES" 55.267,22.889 r0 top
C38 "CQ0402BRNPO9BN2R3" "0402 CAP_IND_RES" 48.667,23.339 r270 top
C39 "CL05B104KO5NNNC" "0402 CAP_IND_RES" 54.745,36.994 r270 bottom
C40 "GJM1555C1H100JB01D" "0402 CAP_IND_RES" 53.245,36.994 r270 bottom
C41 "CL05B104KO5NNNC" "0402 CAP_IND_RES" 46.89,25.456 r0 top
C42 "CL05B104KO5NNNC" "0402 CAP_IND_RES" 46.865,24.027 r0 top
C49 "DNI" 0805_CAP 39.695,17.097 r90 top
C50 "GRM155R71C103KA01D" "0402 CAP_IND_RES" 43.69,18.74 r180 top
C51 "GRM155R61H105KE05D" "0402 CAP_IND_RES" 43.721,17.016 r180 top
C52 "GRM155R71C103KA01D" "0402 CAP_IND_RES" 19.77,27.296 r0 top locked
C53 "GRM155R71C103KA01D" "0402 CAP_IND_RES" 9.7,22.5 r0 top locked
C54 "GRM155R71C103KA01D" "0402 CAP_IND_RES" 25.17,22.496 r0 top locked
C55 "GJM1555C1HR30WB01D" "0402 CAP_IND_RES" 23.22,22.046 r90 top locked
C56 "GRM155R71C103KA01D" "0402 CAP_IND_RES" 37.15,22.496 r180 top locked
C57 "GJM1555C1H1R5BB01D" "0402 CAP_IND_RES" 27.12,22.046 r90 top locked
C58 "GRM155R71C103KA01D" "0402 CAP_IND_RES" 37.15,19.956 r0 top locked
C59 "CL05B104KO5NNNC" "0402 CAP_IND_RES" 33.226,56.608 r0 top
C60 "CL05B104KO5NNNC" "0402 CAP_IND_RES" 33.235,54.858 r0 top
C67 "GRM155R71C103KA01D" "0402 CAP_IND_RES" 29.992,49.741 r180 top
C68 "0805_CAP" 0805_CAP 26.015,48.331 r90 top
C69 "GRM155R61H105KE05D" "0402 CAP_IND_RES" 29.992,48.007 r180 top
C70 "GRM155R71C103KA01D" "0402 CAP_IND_RES" 19.77,57.296 r0 top locked
C71 "GRM155R71C103KA01D" "0402 CAP_IND_RES" 9.7,52.5 r0 top locked
C72 "GRM155R71C103KA01D" "0402 CAP_IND_RES" 25.17,52.496 r0 top locked
C73 "GJM1555C1HR30WB01D" "0402 CAP_IND_RES" 23.22,52.046 r90 top locked
C74 "GJM1555C1HR50CB01D" "0402 CAP_IND_RES" 84.45,33.728 r0 top
C75 "GJM1555C1H390JB01D" "0402 CAP_IND_RES" 93.95,29.818 r90 top
C76 "CL05B104KO5NNNC" "0402 CAP_IND_RES" 86.914,29.403 r90 top
C77 "CL05B104KO5NNNC" "0402 CAP_IND_RES" 81.915,29.348 r270 top
C78 "CL05B104KO5NNNC" "0402 CAP_IND_RES" 86.927,26.838 r90 top
C79 "GJM1555C1H390JB01D" "0402 CAP_IND_RES" 93.95,26.418 r90 top
C80 "GRM155R61H105KE05D" "0402 CAP_IND_RES" 100.319,21.139 r90 top
C81 "GJM1555C1HR50CB01D" "0402 CAP_IND_RES" 84.45,22.508 r0 top
C82 "CL05B104KO5NNNC" "0402 CAP_IND_RES" 81.992,27.152 r90 top
C83 "GRM188C81C106MA73D" 0603_CAP 37.985,38.952 r90 bottom
C84 "GRM188C81C106MA73D" 0603_CAP 30.31,37.109 r90 bottom
C85 "GRM188C81C106MA73D" 0603_CAP 39.12,34.569 r90 bottom
C86 "GRM155R61H105KE05D" "0402 CAP_IND_RES" 30.661,34.013 r90 bottom
C87 "GRM155R61H105KE05D" "0402 CAP_IND_RES" 36.536,33.742 r90 bottom
C88 "GRM155R61H105KE05D" "0402 CAP_IND_RES" 102.063,22.053 r90 top
C89 "GRM155R61H105KE05D" "0402 CAP_IND_RES" 106.718,22.066 r90 top
C90 "GRM155R71C103KA01D" "0402 CAP_IND_RES" 102.067,19.696 r90 top
C91 "GRM155R61H105KE05D" "0402 CAP_IND_RES" 77.978,34.596 r180 top
C92 "GJM1555C1H470FB01D" "0402 CAP_IND_RES" 66.003,29.818 r90 top
C93 "CC0603JRNPO9BN151" 0603_CAP 70.653,30.368 r90 top
C94 "CC0603JRNPO9BN151" 0603_CAP 75.553,30.368 r90 top
C95 "GJM1555C1H470FB01D" "0402 CAP_IND_RES" 66.003,26.418 r90 top
C96 "CC0603JRNPO9BN151" 0603_CAP 70.653,25.868 r90 top
C97 "CC0603JRNPO9BN151" 0603_CAP 75.553,25.868 r90 top
C98 "GRM155R61H105KE05D" "0402 CAP_IND_RES" 77.965,65.227 r180 top
C99 "GJM1555C1H470FB01D" "0402 CAP_IND_RES" 66.003,60.7 r90 top
C100 "CC0603JRNPO9BN151" 0603_CAP 70.653,61.25 r90 top
C101 "CC0603JRNPO9BN151" 0603_CAP 75.553,61.25 r90 top
C102 "GJM1555C1H470FB01D" "0402 CAP_IND_RES" 66.003,57.3 r90 top
C103 "CC0603JRNPO9BN151" 0603_CAP 70.653,56.75 r90 top
C104 "CC0603JRNPO9BN151" 0603_CAP 75.553,56.75 r90 top
C105 "GRM155R61H105KE05D" "0402 CAP_IND_RES" 77.979,50.11 r180 top
C106 "GJM1555C1H470FB01D" "0402 CAP_IND_RES" 66.003,45.7 r90 top
C107 "CC0603JRNPO9BN151" 0603_CAP 70.653,46.25 r90 top
C108 "CC0603JRNPO9BN151" 0603_CAP 75.553,46.25 r90 top
C109 "GJM1555C1H470FB01D" "0402 CAP_IND_RES" 66.003,42.3 r90 top
C110 "CC0603JRNPO9BN151" 0603_CAP 70.653,41.75 r90 top
C111 "CC0603JRNPO9BN151" 0603_CAP 75.553,41.75 r90 top
C112 "GJM1555C1HR50CB01D" "0402 CAP_IND_RES" 84.45,17.179 r0 top
C113 "GJM1555C1H390JB01D" "0402 CAP_IND_RES" 93.95,13.269 r90 top
C114 "CL05B104KO5NNNC" "0402 CAP_IND_RES" 86.961,12.67 r90 top
C115 "CL05B104KO5NNNC" "0402 CAP_IND_RES" 81.956,12.762 r270 top
C116 "CL05B104KO5NNNC" "0402 CAP_IND_RES" 86.961,10.429 r90 top
C117 "GJM1555C1H390JB01D" "0402 CAP_IND_RES" 93.95,9.869 r90 top
C118 "GRM155R61H105KE05D" "0402 CAP_IND_RES" 100.411,4.894 r90 top
C119 "GJM1555C1HR50CB01D" "0402 CAP_IND_RES" 84.45,5.959 r0 top
C120 "CL05B104KO5NNNC" "0402 CAP_IND_RES" 81.971,10.57 r90 top
C121 "GJM1555C1HR50CB01D" "0402 CAP_IND_RES" 84.45,64.61 r0 top
C122 "GJM1555C1H390JB01D" "0402 CAP_IND_RES" 93.95,60.7 r90 top
C123 "CL05B104KO5NNNC" "0402 CAP_IND_RES" 86.88,60.225 r90 top
C124 "CL05B104KO5NNNC" "0402 CAP_IND_RES" 82.072,60.176 r270 top
C125 "CL05B104KO5NNNC" "0402 CAP_IND_RES" 86.87,57.709 r90 top
C126 "GJM1555C1H390JB01D" "0402 CAP_IND_RES" 93.95,57.3 r90 top
C127 "CL05B104KO5NNNC" "0402 CAP_IND_RES" 101.023,52.224 r90 top
C128 "GJM1555C1HR50CB01D" "0402 CAP_IND_RES" 84.45,53.39 r0 top
C129 "CL05B104KO5NNNC" "0402 CAP_IND_RES" 82.165,57.993 r90 top
C130 "GJM1555C1HR50CB01D" "0402 CAP_IND_RES" 84.45,49.61 r0 top
C131 "GJM1555C1H390JB01D" "0402 CAP_IND_RES" 93.95,45.7 r90 top
C132 "CL05B104KO5NNNC" "0402 CAP_IND_RES" 86.934,45.273 r90 top
C133 "CL05B104KO5NNNC" "0402 CAP_IND_RES" 81.968,45.223 r270 top
C134 "CL05B104KO5NNNC" "0402 CAP_IND_RES" 86.937,42.819 r90 top
C135 "GJM1555C1H390JB01D" "0402 CAP_IND_RES" 93.95,42.3 r90 top
C136 "GRM155R61H105KE05D" "0402 CAP_IND_RES" 100.259,37.092 r90 top
C137 "GJM1555C1HR50CB01D" "0402 CAP_IND_RES" 84.45,38.39 r0 top
C138 "CL05B104KO5NNNC" "0402 CAP_IND_RES" 82.219,42.952 r90 top
C139 "GRM155R61H105KE05D" "0402 CAP_IND_RES" 102.163,5.793 r90 top
C140 "GRM155R61H105KE05D" "0402 CAP_IND_RES" 106.848,5.799 r90 top
C141 "GRM155R71C103KA01D" "0402 CAP_IND_RES" 102.186,3.064 r90 top
C142 "GRM155R61H105KE05D" "0402 CAP_IND_RES" 102.75,53.124 r90 top
C143 "GRM155R61H105KE05D" "0402 CAP_IND_RES" 107.423,53.139 r90 top
C144 "GRM155R71C103KA01D" "0402 CAP_IND_RES" 102.667,50.84 r90 top
C145 "GRM155R61H105KE05D" "0402 CAP_IND_RES" 102.009,37.95 r90 top
C146 "GRM155R61H105KE05D" "0402 CAP_IND_RES" 106.828,37.978 r90 top
C147 "GRM155R71C103KA01D" "0402 CAP_IND_RES" 101.988,35.373 r90 top
C148 "CQ0402BRNPO9BN2R3" "0402 CAP_IND_RES" 53.067,20.939 r270 top
C149 "CQ0402BRNPO9BN2R3" "0402 CAP_IND_RES" 53.067,23.339 r90 top
C150 "CL05B104KO5NNNC" "0402 CAP_IND_RES" 118.967,36.02 r90 top
FB1 "MMZ1005A182ET000" "0402 CAP_IND_RES" 19.32,25.346 r90 top locked
FB2 "MMZ1005A182ET000" "0402 CAP_IND_RES" 19.32,22.946 r90 top locked
FB3 "MMZ1005A182ET000" "0402 CAP_IND_RES" 19.32,55.346 r90 top locked
FB4 "MMZ1005A182ET000" "0402 CAP_IND_RES" 19.32,52.946 r90 top locked
HEMEN "TEST_POINT" "TEST POINT" 34.361,64.259 r90 top (schematic designator TPHEMEN)
J1 "1715721" 1715721 28,70 r180 top
J2 "M20-9990245" GND_TEST 93.178,72.982 r180 top
J3 "60312242114510" 60312242114510 2.75,22.5 r270 top locked
J4 "60312242114510" 60312242114510 2.75,52.5 r270 top locked
J5 "60312242114510" 60312242114510 122.25,22.5 r90 top locked
J6 "60312242114510" 60312242114510 122.25,52.5 r90 top locked
J7 "MTP125-1108S1" MTP125-1108S1 62.5,73.205 r0 top
L1 "MWSD1005FR47JTM01" "0402 CAP_IND_RES" 68.203,12.819 r0 top
L2 "SDCL1005CR18JTDF" "0402 CAP_IND_RES" 73.103,12.819 r0 top
L3 "MWSD1005FR47JTM01" "0402 CAP_IND_RES" 68.203,10.319 r0 top
L4 "SDCL1005CR18JTDF" "0402 CAP_IND_RES" 73.103,10.319 r0 top
L9 "LQG15HS1N8S02D" "0402 CAP_IND_RES" 39.85,52.438 r180 top
L10 "LQG15HS1N8S02D" "0402 CAP_IND_RES" 35.45,52.438 r180 top
L11 "SDCL1005C12NJTDF" "0402 CAP_IND_RES" 50.867,21.389 r180 top
L12 "LQG15HS1N8S02D" "0402 CAP_IND_RES" 39.85,53.937 r180 top
L13 "LQG15HS1N8S02D" "0402 CAP_IND_RES" 35.45,53.937 r180 top
L14 "SDCL1005C12NJTDF" "0402 CAP_IND_RES" 50.867,22.889 r180 top
L15 "LQG15HS1N2S02D" "0402 CAP_IND_RES" 13.6,22.5 r0 top locked
L16 "LQG15HS1N2S02D" "0402 CAP_IND_RES" 21.27,22.496 r0 top locked
L17 "LQG15HS5N6B02D" "0402 CAP_IND_RES" 29.07,22.496 r0 top locked
L18 "LQG15HS1N2S02D" "0402 CAP_IND_RES" 13.6,52.5 r0 top locked
L19 "LQG15HS1N2S02D" "0402 CAP_IND_RES" 21.27,52.496 r0 top locked
L20 "LQG15HSR15J02D" "0402 CAP_IND_RES" 90,29.368 r0 top
L21 "LQG15HSR15J02D" "0402 CAP_IND_RES" 96.15,29.368 r0 top
L22 "LQG15HSR15J02D" "0402 CAP_IND_RES" 90,26.868 r0 top
L23 "LQG15HSR15J02D" "0402 CAP_IND_RES" 96.15,26.868 r0 top
L24 "MWSD1005FR47JTM01" "0402 CAP_IND_RES" 68.203,29.368 r0 top
L25 "SDCL1005CR18JTDF" "0402 CAP_IND_RES" 73.103,29.368 r0 top
L26 "MWSD1005FR47JTM01" "0402 CAP_IND_RES" 68.203,26.868 r0 top
L27 "SDCL1005CR18JTDF" "0402 CAP_IND_RES" 73.103,26.868 r0 top
L28 "MWSD1005FR47JTM01" "0402 CAP_IND_RES" 68.203,60.25 r0 top
L29 "SDCL1005CR18JTDF" "0402 CAP_IND_RES" 73.103,60.25 r0 top
L30 "MWSD1005FR47JTM01" "0402 CAP_IND_RES" 68.203,57.75 r0 top
L31 "SDCL1005CR18JTDF" "0402 CAP_IND_RES" 73.103,57.75 r0 top
L32 "MWSD1005FR47JTM01" "0402 CAP_IND_RES" 68.203,45.25 r0 top
L33 "SDCL1005CR18JTDF" "0402 CAP_IND_RES" 73.103,45.25 r0 top
L34 "MWSD1005FR47JTM01" "0402 CAP_IND_RES" 68.203,42.75 r0 top
L35 "SDCL1005CR18JTDF" "0402 CAP_IND_RES" 73.103,42.75 r0 top
L36 "LQG15HSR15J02D" "0402 CAP_IND_RES" 90,12.819 r0 top
L37 "LQG15HSR15J02D" "0402 CAP_IND_RES" 96.15,12.819 r0 top
L38 "LQG15HSR15J02D" "0402 CAP_IND_RES" 90,10.319 r0 top
L39 "LQG15HSR15J02D" "0402 CAP_IND_RES" 96.15,10.319 r0 top
L40 "LQG15HSR15J02D" "0402 CAP_IND_RES" 90,60.25 r0 top
L41 "LQG15HSR15J02D" "0402 CAP_IND_RES" 96.15,60.25 r0 top
L42 "LQG15HSR15J02D" "0402 CAP_IND_RES" 90,57.75 r0 top
L43 "LQG15HSR15J02D" "0402 CAP_IND_RES" 96.15,57.75 r0 top
L44 "LQG15HSR15J02D" "0402 CAP_IND_RES" 90,45.25 r0 top
L45 "LQG15HSR15J02D" "0402 CAP_IND_RES" 96.15,45.25 r0 top
L46 "LQG15HSR15J02D" "0402 CAP_IND_RES" 90,42.75 r0 top
L47 "LQG15HSR15J02D" "0402 CAP_IND_RES" 96.15,42.75 r0 top
LEMEN "TEST_POINT" "TEST POINT" 36.74,70.461 r90 top (schematic designator TPLEMEN)
LOADEN "TEST_POINT" "TEST POINT" 36.849,60.994 r90 top (schematic designator TPLOADEN)
MH "Comment" "MOUNTING HOLE" 5,70 r0 top locked
MH "Comment" "MOUNTING HOLE" 120,70 r0 top locked
MH "Comment" "MOUNTING HOLE" 120,5 r0 top locked
MH "Comment" "MOUNTING HOLE" 5,5 r0 top locked
MH "Comment" "MOUNTING HOLE" 62.5,37.5 r0 top locked
MUXOUT "TEST_POINT" "TEST POINT" 42,37.5 r90 top (schematic designator TPMUXOUT)
R1 "CRCW0402110RFKED" "0402 CAP_IND_RES" 77.553,9.869 r90 top
R2 "CRCW0402110RFKED" "0402 CAP_IND_RES" 77.553,13.269 r90 top
R3 "CRCW040220R0FKED" "0402 CAP_IND_RES" 79.753,12.819 r0 top
R4 "CRCW040220R0FKED" "0402 CAP_IND_RES" 79.753,10.319 r0 top
R5 "RC0402JR-071KL" "0402 CAP_IND_RES" 52.795,27.856 r90 bottom
R6 "CRCW040251R0FKED" 0603_CAP 42.978,31.709 r0 bottom
R7 "RC0402FR-07360RL" "0402 CAP_IND_RES" 54.295,25.606 r270 bottom
R8 "CRCW0402110RFKED" "0402 CAP_IND_RES" 54.295,27.856 r90 bottom
R9 "CRCW040210K0FKEDC" "0402 CAP_IND_RES" 46.068,48.13 r180 bottom
R10 "DNI" "0402 CAP_IND_RES" 46.068,46.38 r180 bottom
R11 "0402WGF4701TCE" "0402 CAP_IND_RES" 48.496,30.374 r270 bottom
R12 "CRCW040210K0FKEDC" "0402 CAP_IND_RES" 46.068,44.63 r0 bottom
R13 "CRCW040210K0FKEDC" "0402 CAP_IND_RES" 46.068,42.88 r0 bottom
R14 "CRCW040210K0FKEDC" "0402 CAP_IND_RES" 46.068,41.13 r0 bottom
R15 "0402_RES" "0402 CAP_IND_RES" 41.82,17.819 r90 top
R16 "CRCW040210K0FKEDC" "0402 CAP_IND_RES" 11.65,22.05 r90 top locked
R17 "0402_RES" "0402 CAP_IND_RES" 28.134,49.298 r90 top
R18 "CRCW040210K0FKEDC" "0402 CAP_IND_RES" 11.65,52.05 r90 top locked
R19 "RC-02K3920FT" "0402 CAP_IND_RES" 84.45,31.728 r0 top
R20 "RC0402FR-07240RL" "0402 CAP_IND_RES" 90,31.368 r0 top
R21 "CRCW040220R0FKED" "0402 CAP_IND_RES" 87.1,31.728 r0 top
R22 "FRC0402F82R0TS" "0402 CAP_IND_RES" 96.15,31.368 r0 top
R23 "RC0402FR-0727RL" "0402 CAP_IND_RES" 92.2,29.818 r90 top
R24 "RC0402FR-0727RL" "0402 CAP_IND_RES" 92.2,26.418 r90 top
R25 "CRCW0402150RFKED" "0402 CAP_IND_RES" 98.021,25.413 r270 top
R26 "CRCW0402150RFKED" "0402 CAP_IND_RES" 98.053,28.193 r270 top
R27 "RC0402FR-07240RL" "0402 CAP_IND_RES" 90,24.868 r0 top
R28 "CRCW040220R0FKED" "0402 CAP_IND_RES" 87.1,24.508 r0 top
R29 "FRC0402F82R0TS" "0402 CAP_IND_RES" 96.15,24.868 r0 top
R30 "RC-02K3920FT" "0402 CAP_IND_RES" 84.45,24.508 r0 top
R31 "CRCW0402100RFKEDHP" "0402 CAP_IND_RES" 97.526,23.143 r0 top
R32 "CRCW0402110RFKED" "0402 CAP_IND_RES" 77.553,26.418 r90 top
R33 "CRCW0402110RFKED" "0402 CAP_IND_RES" 77.553,29.818 r90 top
R34 "CRCW040220R0FKED" "0402 CAP_IND_RES" 79.753,29.368 r0 top
R35 "CRCW040220R0FKED" "0402 CAP_IND_RES" 79.753,26.868 r0 top
R36 "CRCW0402110RFKED" "0402 CAP_IND_RES" 77.553,57.3 r90 top
R37 "CRCW0402110RFKED" "0402 CAP_IND_RES" 77.553,60.7 r90 top
R38 "CRCW040220R0FKED" "0402 CAP_IND_RES" 79.753,60.25 r0 top
R39 "CRCW040220R0FKED" "0402 CAP_IND_RES" 79.753,57.75 r0 top
R40 "CRCW0402110RFKED" "0402 CAP_IND_RES" 77.553,42.3 r90 top
R41 "CRCW0402110RFKED" "0402 CAP_IND_RES" 77.553,45.7 r90 top
R42 "CRCW040220R0FKED" "0402 CAP_IND_RES" 79.753,45.25 r0 top
R43 "CRCW040220R0FKED" "0402 CAP_IND_RES" 79.753,42.75 r0 top
R44 "RC-02K3920FT" "0402 CAP_IND_RES" 84.45,15.179 r0 top
R45 "RC0402FR-07240RL" "0402 CAP_IND_RES" 90,14.819 r0 top
R46 "CRCW040220R0FKED" "0402 CAP_IND_RES" 87.1,15.179 r0 top
R47 "FRC0402F82R0TS" "0402 CAP_IND_RES" 96.15,14.819 r0 top
R48 "RC0402FR-0727RL" "0402 CAP_IND_RES" 92.2,13.269 r90 top
R49 "RC0402FR-0727RL" "0402 CAP_IND_RES" 92.2,9.869 r90 top
R50 "CRCW0402150RFKED" "0402 CAP_IND_RES" 97.959,8.859 r270 top
R51 "CRCW0402150RFKED" "0402 CAP_IND_RES" 97.986,11.625 r270 top
R52 "CRCW0402243RFKED" "0402 CAP_IND_RES" 90,8.319 r0 top
R53 "CRCW040220R0FKED" "0402 CAP_IND_RES" 87.1,7.959 r0 top
R54 "FRC0402F82R0TS" "0402 CAP_IND_RES" 96.15,8.319 r0 top
R55 "RC-02K3920FT" "0402 CAP_IND_RES" 84.45,7.959 r0 top
R56 "CRCW0402100RFKEDHP" "0402 CAP_IND_RES" 97.508,6.57 r0 top
R57 "RC-02K3920FT" "0402 CAP_IND_RES" 84.45,62.61 r0 top
R58 "RC0402FR-07240RL" "0402 CAP_IND_RES" 90,62.25 r0 top
R59 "CRCW040220R0FKED" "0402 CAP_IND_RES" 87.1,62.61 r0 top
R60 "FRC0402F82R0TS" "0402 CAP_IND_RES" 96.15,62.25 r0 top
R61 "RC0402FR-0727RL" "0402 CAP_IND_RES" 92.2,60.7 r90 top
R62 "RC0402FR-0727RL" "0402 CAP_IND_RES" 92.2,57.3 r90 top
R63 "CRCW0402150RFKED" "0402 CAP_IND_RES" 98.044,56.388 r270 top
R64 "CRCW0402150RFKED" "0402 CAP_IND_RES" 97.971,59.064 r270 top
R65 "RC0402FR-07240RL" "0402 CAP_IND_RES" 90,55.75 r0 top
R66 "CRCW040220R0FKED" "0402 CAP_IND_RES" 87.1,55.39 r0 top
R67 "FRC0402F82R0TS" "0402 CAP_IND_RES" 96.15,55.75 r0 top
R68 "RC-02K3920FT" "0402 CAP_IND_RES" 84.45,55.39 r0 top
R69 "CRCW0402100RFKEDHP" "0402 CAP_IND_RES" 97.626,54.017 r0 top
R70 "RC-02K3920FT" "0402 CAP_IND_RES" 84.45,47.61 r0 top
R71 "RC0402FR-07240RL" "0402 CAP_IND_RES" 90,47.25 r0 top
R72 "CRCW040220R0FKED" "0402 CAP_IND_RES" 87.1,47.61 r0 top
R73 "FRC0402F82R0TS" "0402 CAP_IND_RES" 96.15,47.25 r0 top
R74 "RC0402FR-0727RL" "0402 CAP_IND_RES" 92.2,45.7 r90 top
R75 "RC0402FR-0727RL" "0402 CAP_IND_RES" 92.2,42.3 r90 top
R76 "CRCW0402150RFKED" "0402 CAP_IND_RES" 98.008,41.223 r270 top
R77 "CRCW0402150RFKED" "0402 CAP_IND_RES" 98.053,44.091 r270 top
R78 "RC0402FR-07240RL" "0402 CAP_IND_RES" 90,40.75 r0 top
R79 "CRCW040220R0FKED" "0402 CAP_IND_RES" 87.1,40.39 r0 top
R80 "FRC0402F82R0TS" "0402 CAP_IND_RES" 96.15,40.75 r0 top
R81 "RC-02K3920FT" "0402 CAP_IND_RES" 84.45,40.39 r0 top
R82 "CRCW0402100RFKEDHP" "0402 CAP_IND_RES" 97.56,38.968 r0 top
R83 "AC0402JR-0750RL" "0402 CAP_IND_RES" 57.217,23.339 r90 top
R84 "AC0402JR-0750RL" "0402 CAP_IND_RES" 57.217,20.939 r270 top
R85 "AC0402JR-0750RL" "0402 CAP_IND_RES" 44.2,54.387 r90 top
R86 "AC0402JR-0750RL" "0402 CAP_IND_RES" 44.2,51.988 r270 top
SWI "TEST_POINT" "TEST POINT" 99.291,70.703 r90 top (schematic designator TPSWI)
SWQ "TEST_POINT" "TEST POINT" 99.033,65.608 r90 top (schematic designator TPSWQ)
T1 "TC1-1-13M+" TC1-1-13M+ 102.75,28.118 r270 top
T2 "TC1-1-13M+" TC1-1-13M+ 102.75,11.569 r270 top
T3 "TC1-1-13M+" TC1-1-13M+ 102.75,59 r270 top
T4 "TC1-1-13M+" TC1-1-13M+ 102.75,44 r270 top
T5 "TC1-1-13M+" TC1-1-13M+ 33.11,21.226 r270 top locked
U1 "ADG736BRMZ" ADG736BRMZ 114.345,36.466 r0 top
U2 "MCP23S17T-E_ML" MCP23S17T-E_ML 44.75,65.5 r180 top
U3 "ADF4351BCPZ" ADF4351BCPZ 49.495,35.244 r270 bottom
U4 "LTC5584IUF#PBF" LTC5584/LTC5585 42.981,22.159 r0 top
U5 "QPL7442TR7" QPL7442TR7 16.435,22.25 r0 top locked
U6 "LTC5585IUF#PBF" LTC5584/LTC5585 29.255,53.223 r0 top
U7 "QPL7442TR7" QPL7442TR7 16.435,52.25 r0 top locked
U8 "LTC6409IUDB#TRMPBF" LTC6409IUDB#TRMPBF 84.4,28.118 r270 top
U9 "ADM7150ACPZ-3.3-R7" ADM7150ACPZ-3.3-R7 33.795,35.32 r180 bottom
U10 "TPS71709DSER" TPS71709DSER 104.284,21.114 r0 top
U11 "LTC6409IUDB#TRMPBF" LTC6409IUDB#TRMPBF 84.4,11.569 r270 top
U12 "LTC6409IUDB#TRMPBF" LTC6409IUDB#TRMPBF 84.4,59 r270 top
U13 "LTC6409IUDB#TRMPBF" LTC6409IUDB#TRMPBF 84.4,44 r270 top
U14 "TPS71709DSER" TPS71709DSER 104.373,4.83 r0 top
U15 "TPS71709DSER" TPS71709DSER 104.901,52.162 r0 top
U16 "TPS71709DSER" TPS71709DSER 104.213,36.995 r0 top
VCC "TEST_POINT" "TEST POINT" 17.602,70.053 r90 top (schematic designator TPVCC)

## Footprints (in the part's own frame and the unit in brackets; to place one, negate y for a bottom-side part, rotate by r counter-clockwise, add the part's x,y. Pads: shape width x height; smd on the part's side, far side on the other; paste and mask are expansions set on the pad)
"0402 CAP_IND_RES" [mm]
  rect 0.5x0.5 smd mask+0.035: 1(-0.45,0) 2(0.45,0)
  body extent -0.53,-0.27 0.54,0.24, height 0.71
0603_CAP [mm]
  rect 1x1.2 smd mask+0.035: 1(-1,0) 2(1,0)
  body extent -0.8,-0.41 0.8,0.41, height 0.71
0805_CAP [mm]
  rect 1.2x1.3 smd mask+0.035: 1(-1.1,0) 2(1.1,0)
1715721 [mil] "PS CONNECTOR"
  round 71 / inner round 60 / far side round 71 hole 51.18 paste-99999 mask+0: 1(0,0) 2(200,0)
  Keep-Out Layer region: -102.95,-195.87 302.95,-195.87 302.95,195.87 -102.95,195.87
  silkscreen extent -107,-202 307,202, body extent -121,-185 301,202, height 559
60312242114510 [mm] "FEMALE SMA - EDGE MOUNT"
  rect 2.8x5 smd mask+0.1: 1(-3.55,0) 3(3.55,0)
  rect 0.9x5 smd mask+0.1: 2(0,0)
  rect 2.8x5 smd far side mask+0.1: 4(-3.55,0) 5(3.55,0)
  Keep-Out Layer region: -4.76,-2.375 4.76,-2.375 4.76,2.375 -4.76,2.375
  silkscreen extent -5.75,-3.18 5.75,3.32, body extent -4.76,-15.24 4.76,2.21, height 4.36
ADF4351BCPZ [mm] "WIDEBAND SYNTHESIZER"
  round 0.025 smd mask+0.05: 1(-2.286,1.75) 8(-2.286,-1.75) 9(-1.75,-2.286) 16(1.75,-2.286) 17(2.286,-1.75) 24(2.286,1.75) 25(1.75,2.286) 32(-1.75,2.286)
  rect 0.5x0.3 smd mask+0.05: 2(-2.286,1.25) 3(-2.286,0.75) 4(-2.286,0.25) 5(-2.286,-0.25) 6(-2.286,-0.75) 7(-2.286,-1.25) 18(2.286,-1.25) 19(2.286,-0.75) 20(2.286,-0.25) 21(2.286,0.25) 22(2.286,0.75) 23(2.286,1.25)
  rect 0.3x0.5 smd mask+0.05: 10(-1.25,-2.286) 11(-0.75,-2.286) 12(-0.25,-2.286) 13(0.25,-2.286) 14(0.75,-2.286) 15(1.25,-2.286) 26(1.25,2.286) 27(0.75,2.286) 28(0.25,2.286) 29(-0.25,2.286) 30(-0.75,2.286) 31(-1.25,2.286)
  rect 3.1x3.1 smd mask+0.05: 33(0,0)
  Top Layer (RF) region: -1.9,2.111 -1.9,2.536 -1.6,2.536 -1.6,2.036 -1.825,2.036
  Top Layer (RF) region: 1.6,2.036 1.6,2.536 1.9,2.536 1.9,2.111 1.825,2.036
  Top Layer (RF) region: 2.111,1.9 2.536,1.9 2.536,1.6 2.036,1.6 2.036,1.825
  Top Layer (RF) region: 2.036,-1.6 2.536,-1.6 2.536,-1.9 2.111,-1.9 2.036,-1.825
  Top Layer (RF) region: 1.9,-2.111 1.9,-2.536 1.6,-2.536 1.6,-2.036 1.825,-2.036
  Top Layer (RF) region: -1.6,-2.036 -1.6,-2.536 -1.9,-2.536 -1.9,-2.111 -1.825,-2.036
  Top Layer (RF) region: -2.111,-1.9 -2.536,-1.9 -2.536,-1.6 -2.036,-1.6 -2.036,-1.825
  Top Layer (RF) region: -2.036,1.6 -2.536,1.6 -2.536,1.9 -2.111,1.9 -2.036,1.825
  Keep-Out Layer region: -2.54,2.54 2.54,2.54 2.54,-2.54 -2.54,-2.54
  silkscreen extent -2.84,-2.5 2.5,2.72, body extent -2.5,-2.5 2.5,2.5, height 0.8
ADG736BRMZ [mm] "SWITCH - SPDT"
  rect 0.7x0.3 smd mask-2539.97: 1(-2.45,1) 2(-2.45,0.5) 3(-2.45,0) 4(-2.45,-0.5) 5(-2.45,-1) 6(2.45,-1) 7(2.45,-0.5) 8(2.45,0) 9(2.45,0.5) 10(2.45,1)
  Keep-Out Layer region: -2.45,-1.5 2.45,-1.5 2.45,1.5 -2.45,1.5
  silkscreen extent -3.15,-1.63 3.15,1.95, body extent -2.45,-1.5 2.45,1.5, height 1.1
ADM7150ACPZ-3.3-R7 [mm] "3.3V REG"
  round 0.025 smd mask-2539.97: 1(-1.275,0.75) 2(-1.275,0.25) 3(-1.275,-0.25) 4(-1.275,-0.75) 5(1.275,-0.75) 6(1.275,-0.25) 7(1.275,0.25) 8(1.275,0.75)
  rect 1.6x2.34 smd mask+0.102: 9(0,0)
  Top Layer (RF) region: 1.2,0.875 1.475,0.875 1.475,0.625 1.2,0.625 1.152,0.635 1.112,0.662 1.085,0.702 1.075,0.75 1.075,0.75 1.085,0.798 1.112,0.838 1.152,0.865 1.2,0.875
  Top Layer (RF) region: 1.2,0.375 1.475,0.375 1.475,0.125 1.2,0.125 1.152,0.135 1.112,0.162 1.085,0.202 1.075,0.25 1.075,0.25 1.085,0.298 1.112,0.338 1.152,0.365 1.2,0.375
  Top Layer (RF) region: 1.2,-0.125 1.475,-0.125 1.475,-0.375 1.2,-0.375 1.152,-0.365 1.112,-0.338 1.085,-0.298 1.075,-0.25 1.075,-0.25 1.085,-0.202 1.112,-0.162 1.152,-0.135 1.2,-0.125
  Top Layer (RF) region: 1.2,-0.625 1.475,-0.625 1.475,-0.875 1.2,-0.875 1.152,-0.865 1.112,-0.838 1.085,-0.798 1.075,-0.75 1.075,-0.75 1.085,-0.702 1.112,-0.662 1.152,-0.635 1.2,-0.625
  Top Layer (RF) region: -1.2,-0.875 -1.475,-0.875 -1.475,-0.625 -1.2,-0.625 -1.152,-0.635 -1.112,-0.662 -1.085,-0.702 -1.075,-0.75 -1.075,-0.75 -1.085,-0.798 -1.112,-0.838 -1.152,-0.865 -1.2,-0.875
  Top Layer (RF) region: -1.2,-0.375 -1.475,-0.375 -1.475,-0.125 -1.2,-0.125 -1.152,-0.135 -1.112,-0.162 -1.085,-0.202 -1.075,-0.25 -1.075,-0.25 -1.085,-0.298 -1.112,-0.338 -1.152,-0.365 -1.2,-0.375
  Top Layer (RF) region: -1.2,0.125 -1.475,0.125 -1.475,0.375 -1.2,0.375 -1.152,0.365 -1.112,0.338 -1.085,0.298 -1.075,0.25 -1.075,0.25 -1.085,0.202 -1.112,0.162 -1.152,0.135 -1.2,0.125
  Top Layer (RF) region: -1.2,0.625 -1.475,0.625 -1.475,0.875 -1.2,0.875 -1.152,0.865 -1.112,0.838 -1.085,0.798 -1.075,0.75 -1.075,0.75 -1.085,0.702 -1.112,0.662 -1.152,0.635 -1.2,0.625
  Keep-Out Layer region: -1.5,1.5 1.5,1.5 1.5,-1.5 -1.5,-1.5
  silkscreen extent -1.83,-1.5 1.5,1.5, body extent -1.55,-1.5 1.55,1.5, height 0.85
GND_TEST [mm] "TEST POINT FOR GND HEADER"
  round 1.605 hole 1.02: 1(-1.27,0) 2(1.27,0)
  Keep-Out Layer region: -2.54,-1.27 2.54,-1.27 2.54,1.27 -2.54,1.27
  silkscreen extent -3.1,-1.27 2.54,1.57, body extent -2.57,-1.26 2.51,1.28, height 8.65
LTC5584/LTC5585 [mm] "MIXERS /  / LTC5585IUF#PBF / LTC5584IUF#PBF"
  rect 0.7x0.25 smd mask+0.05: 1(-1.9,1.25) 2(-1.9,0.75) 3(-1.9,0.25) 4(-1.9,-0.25) 5(-1.9,-0.75) 6(-1.9,-1.25) 13(1.9,-1.25) 14(1.9,-0.75) 15(1.9,-0.25) 16(1.9,0.25) 17(1.9,0.75) 18(1.9,1.25)
  rect 0.25x0.7 smd mask+0.05: 7(-1.25,-1.9) 8(-0.75,-1.9) 9(-0.25,-1.9) 10(0.25,-1.9) 11(0.75,-1.9) 12(1.25,-1.9) 19(1.25,1.9) 20(0.75,1.9) 21(0.25,1.9) 22(-0.25,1.9) 23(-0.75,1.9) 24(-1.25,1.9)
  round 0.025 smd mask-2539.97: 25(0,0)
  Top Layer (RF) region: 1.225,1.225 1.225,-1.225 -1.225,-1.225 -1.225,0.825 -0.825,1.225
  Keep-Out Layer region: -2.05,-2.05 2.05,-2.05 2.05,2.05 -2.05,2.05
  silkscreen extent -2.46,-2 2,2, body extent -2.05,-2.05 2.05,2.05, height 0.8
LTC6409IUDB#TRMPBF [mm] "DIFFERENTAL OP-AMP"
  round 0.025 smd mask-2539.97: 1(-1.275,0.4) 2(-1.325,-0.4) 3(-0.5,-0.875) 4(0,-0.875) 5(0.5,-0.875) 6(1.325,-0.4) 7(1.325,0.4) 8(0.5,0.925) 9(0,0.925) 10(-0.5,0.925)
  rect 0.9x0.25 smd mask-2539.97: 11(0,0.05)
  Top Layer (RF) region: -0.625,0.725 -0.625,1.25 -0.375,1.25 -0.375,0.725 -0.385,0.677 -0.412,0.637 -0.452,0.61 -0.5,0.6 -0.5,0.6 -0.548,0.61 -0.588,0.637 -0.615,0.677 -0.625,0.725
  Top Layer (RF) region: -0.125,0.725 -0.125,1.25 0.125,1.25 0.125,0.725 0.115,0.677 0.088,0.637 0.048,0.61 0,0.6 0,0.6 -0.048,0.61 -0.088,0.637 -0.115,0.677 -0.125,0.725
  Top Layer (RF) region: 0.375,0.725 0.375,1.25 0.625,1.25 0.625,0.725 0.615,0.677 0.588,0.637 0.548,0.61 0.5,0.6 0.5,0.6 0.452,0.61 0.412,0.637 0.385,0.677 0.375,0.725
  Top Layer (RF) region: -0.8,0.275 -1.75,0.275 -1.75,0.525 -0.925,0.525 -0.8,0.4
  Top Layer (RF) region: -1.025,-0.525 -1.75,-0.525 -1.75,-0.275 -1.025,-0.275 -0.977,-0.285 -0.937,-0.312 -0.91,-0.352 -0.9,-0.4 -0.9,-0.4 -0.91,-0.448 -0.937,-0.488 -0.977,-0.515 -1.025,-0.525
  Top Layer (RF) region: -0.375,-0.625 -0.375,-1.25 -0.625,-1.25 -0.625,-0.625 -0.615,-0.577 -0.588,-0.537 -0.548,-0.51 -0.5,-0.5 -0.5,-0.5 -0.452,-0.51 -0.412,-0.537 -0.385,-0.577 -0.375,-0.625
  Top Layer (RF) region: 0.125,-0.625 0.125,-1.25 -0.125,-1.25 -0.125,-0.625 -0.115,-0.577 -0.088,-0.537 -0.048,-0.51 0,-0.5 0,-0.5 0.048,-0.51 0.088,-0.537 0.115,-0.577 0.125,-0.625
  Top Layer (RF) region: 0.625,-0.625 0.625,-1.25 0.375,-1.25 0.375,-0.625 0.385,-0.577 0.412,-0.537 0.452,-0.51 0.5,-0.5 0.5,-0.5 0.548,-0.51 0.588,-0.537 0.615,-0.577 0.625,-0.625
  Top Layer (RF) region: 1.025,-0.275 1.75,-0.275 1.75,-0.525 1.025,-0.525 0.977,-0.515 0.937,-0.488 0.91,-0.448 0.9,-0.4 0.9,-0.4 0.91,-0.352 0.937,-0.312 0.977,-0.285 1.025,-0.275
  Top Layer (RF) region: 1.025,0.525 1.75,0.525 1.75,0.275 1.025,0.275 0.977,0.285 0.937,0.312 0.91,0.352 0.9,0.4 0.9,0.4 0.91,0.448 0.937,0.488 0.977,0.515 1.025,0.525
  Keep-Out Layer region: -1.5,-1 1.5,-1 1.5,1 -1.5,1
  silkscreen extent -1.93,-1 1.5,1.17, body extent -1.52,-1.02 1.52,1.02, height 0.8
MCP23S17T-E_ML [mm] "I/O EXPANDER"
  rect 1x0.37 smd mask+0.04: 1(-2.85,1.95) 2(-2.85,1.3) 3(-2.85,0.65) 4(-2.85,0) 5(-2.85,-0.65) 6(-2.85,-1.3) 7(-2.85,-1.95) 15(2.85,-1.95) 16(2.85,-1.3) 17(2.85,-0.65) 18(2.85,0) 19(2.85,0.65) 20(2.85,1.3) 21(2.85,1.95)
  rect 0.37x1 smd mask+0.04: 8(-1.95,-2.85) 9(-1.3,-2.85) 10(-0.65,-2.85) 11(0,-2.85) 12(0.65,-2.85) 13(1.3,-2.85) 14(1.95,-2.85) 22(1.95,2.865) 23(1.3,2.865) 24(0.65,2.865) 25(0,2.865) 26(-0.65,2.865) 27(-1.3,2.865) 28(-1.95,2.865)
  round 0.025 smd mask-2539.97: 29(0,0)
  Top Layer (RF) region: 2.1,2.1 2.1,-2.1 -2.1,-2.1 -2.1,1.68 -1.68,2.1
  Keep-Out Layer region: -3,-3 3,-3 3,3 -3,3
  silkscreen extent -3.53,-3 3,3.27, body extent -3.06,-3.06 3.04,3.04, height 1
"MOUNTING HOLE" [mm] "NOT CONNECTED TP GROUND"
  round 0 hole 4 unplated paste-2539.97: MH(0,0)
MTP125-1108S1 [mm] "Direct Insert Policy 2.5mm 8P 6mm -40℃~+105℃ 3mm 2.54mm Single Row Black Brass 1x8P Plugin,P=2.54mm Pin Headers ROHS"
  round 1.605 hole 1.02: 1(-8.89,0) 2(-6.35,0) 3(-3.81,0) 4(-1.27,0) 5(1.27,0) 6(3.81,0) 7(6.35,0) 8(8.89,0)
  Keep-Out Layer region: -10.16,-1.27 10.16,-1.27 10.16,1.27 -10.16,1.27
  silkscreen extent -10.7,-1.27 10.16,1.27, body extent -10.19,-1.31 10.13,1.23, height 6.1
QPL7442TR7 [mm] "LNA"
  rect 0.67x0.3 smd mask+0.05: 1(-0.885,0.75) 2(-0.885,0.25) 3(-0.885,-0.25) 4(-0.885,-0.75) 5(0.885,-0.754) 6(0.885,-0.254) 7(0.885,0.246) 8(0.885,0.746)
  rect 0.7x1.6 smd mask+0.05: 9(0,0)
  Keep-Out Layer region: -1,-1 1,-1 1,1 -1,1
  silkscreen extent -1.43,-1.16 1,1.17, body extent -1.05,-1 1.05,1, height 0.95
TC1-1-13M+ [mm] "1:1 BALUN,"
  rect 0.76x1.65 smd: 1(-1.27,1.59) 2(0,1.59) 3(1.27,1.59) 4(1.27,-1.59) 6(-1.27,-1.59)
  Keep-Out Layer region: -1.98,-1.905 1.98,-1.905 1.98,1.905 -1.98,1.905
  silkscreen extent -2.34,-1.91 1.91,2.46, body extent -1.91,-1.91 1.91,1.91, height 4.06
"TEST POINT" [mm] "TEST POINT"
  round 1.5 hole 1: 1(0,0)
TPS71709DSER [mm] "0.9V REG (DSE)"
  rrect40% 0.25x0.25 smd mask+0.05: 1(-0.55,0.5)
  rrect40% 0.7x0.25 smd mask+0.05: 2(-0.6,0) 3(-0.6,-0.5) 4(0.6,-0.5) 5(0.6,0) 6(0.6,0.5)
  Top Layer (RF) region: -0.9,0.375 -0.919,0.379 -0.935,0.39 -0.946,0.406 -0.95,0.425 -0.95,0.425 -0.95,0.575 -0.946,0.594 -0.935,0.61 -0.919,0.621 -0.9,0.625 -0.9,0.625 -0.2,0.625 -0.181,0.621 -0.165,0.61 -0.154,0.594 -0.15,0.575 -0.15,0.575 -0.15,0.425 -0.154,0.406 -0.165,0.39 -0.181,0.379 -0.2,0.375 -0.2,0.375
  Keep-Out Layer region: -0.775,-0.775 0.775,-0.775 0.775,0.775 -0.775,0.775
  silkscreen extent -1.17,-0.93 0.77,1.05, body extent -0.75,-0.75 0.75,0.75, height 0.8

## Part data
C1 C51 C69 C80 C86 C87 C88 C89 C91 C98 C105 C127 C136 C139 C140 C142 C143 C145 C146: library part 0402_CAP, "50V 1uF X5R ±10% 0402  Multilayer Ceramic Capacitors MLCC - SMD/SMT ROHS", CAPACITANCE=1uF
C2 C5 C92 C95 C99 C102 C106 C109: library part 0402_CAP, "50V 47pF null ±1% 0402  Multilayer Ceramic Capacitors MLCC - SMD/SMT ROHS", CAPACITANCE=47pF
C3 C4 C6 C7 C93 C94 C96 C97 C100 C101 C103 C104 C107 C108 C110 C111: library part 0603_CAP, "50V 150pF NP0 ±5% 0603 Multilayer Ceramic Capacitors MLCC - SMD/SMT ROHS", CAPACITANCE=150pF
C8 C9: library part 0805_CAP, "50V 1nF C0G ±1% 0402 Multilayer Ceramic Capacitors MLCC - SMD/SMT ROHS", CAPACITANCE=1nF
C10: library part 0402_CAP, "50V 2.7nF X7R ±10% 0402 Multilayer Ceramic Capacitors MLCC - SMD/SMT ROHS", CAPACITANCE=2.7nF
C11: library part 0402_CAP, "Ceramic Capacitor for Automotive 680pF ±5% 50VDC C0G 0402 Paper T/R", CAPACITANCE=680pF
C12: library part 0402_CAP, "50V 39pF C0G ±5% 0402 Multilayer Ceramic Capacitors MLCC - SMD/SMT ROHS", CAPACITANCE=39nF
C13 C15 C18 C21 C22 C23 C26 C39 C41 C42 C59 C60 C76 C77 C78 C82 C114 C115 C116 C120 C123 C124 C125 C129 C132 C133 C134 C138 C150: library part 0402_CAP, "16V 100nF X7R ±10% 0402 Multilayer Ceramic Capacitors MLCC - SMD/SMT ROHS", CAPACITANCE=0.1uF
C14 C16 C17 C19 C20 C24 C25 C40: library part 0402_CAP, "Multi-Layer Ceramic Capacitor 10pF C0G  ±5% 0402 Paper T/R", CAPACITANCE=10pF
C27 C38 C148 C149: library part 0402_CAP, "50V 2.3pF C0G 0402 Multilayer Ceramic Capacitors MLCC - SMD/SMT ROHS", CAPACITANCE=2.3pF
C29 C34: library part 0402_CAP, "50V 1.5pF C0G 0402 Multilayer Ceramic Capacitors MLCC - SMD/SMT ROHS", CAPACITANCE=1.5pF
C30 C32 C33 C36: library part 0402_CAP, "50V 1nF C0G ±5% 0402 Multilayer Ceramic Capacitors MLCC - SMD/SMT ROHS", CAPACITANCE=1nF
C49: library part 0805_CAP
C50 C52 C53 C54 C56 C58 C67 C70 C71 C72 C90 C141 C144 C147: library part 0402_CAP, "Chip Capacitor, 10 nF, 16 V, 10%, -55 to 125 degC, 0402 (1005 Metric), RoHS, Tape and Reel", CAPACITANCE=0.01uF
C55 C73: library part 0402_CAP, "Multi-Layer Ceramic Capacitor 0.3pF C0G  ±0.05pF 0402 Paper T/R", CAPACITANCE=0.3pF
C57: library part 0402_CAP, "Multi-Layer Ceramic Capacitor 1.5pF C0G  ±0.1pF 0402 Paper T/R", CAPACITANCE=1.5pF
C68 R15 R17: "DNI"
C74 C81 C112 C119 C121 C128 C130 C137: library part 0402_CAP, "Multi-Layer Ceramic Capacitor 0.5pF C0G  ±0.25pF 0402 Paper T/R", CAPACITANCE=0.5pF
C75 C79 C113 C117 C122 C126 C131 C135: library part 0402_CAP, "Multi-Layer Ceramic Capacitor 39pF C0G  ±5% 0402 Paper T/R", CAPACITANCE=39pF
C83 C84 C85: library part 0603_CAP, "Chip Multilayer Ceramic Capacitors for General Purpose, 0603, 10uF, X6S, 22%, 20%, 16V", CAPACITANCE=10uF
C118: library part 0402_CAP, "CAPACITOR", CAPACITANCE=1uF
FB1 FB2 FB3 FB4: library part 0402_FERRITE_BEADS, "Signal Line Ferrite Bead 1800Ω @ 100MHz 200mA DCR 2100mΩ SMD 0402"
HEMEN LEMEN LOADEN MUXOUT SWI SWQ VCC: "TEST POINT"
J1: "1x2P 17.5A 250V Green 14~30 Direct Insert 5.08mm 1 2 Plugin,P=5.08mm Screw Terminal Blocks ROHS", Mfr_Name="Phoenix Contact"
J2: library part GND_TEST, "3A Direct Insert Policy 2.54mm 2P 6.1mm -40℃~+105℃ 3mm 2.54mm Single Row Brass Black Plugin,P=2.54mm  Pin Headers ROHS", Mfr_Name=Harwin
J3 J4 J5 J6: "1 SMA Board Edge 18GHz 50Ω -  RF Connectors / Coaxial Connectors ROHS"
J7: "Direct Insert Policy 2.5mm 8P 6mm -40℃~+105℃ 3mm 2.54mm Single Row Black Brass 1x8P Plugin,P=2.54mm Pin Headers ROHS", Package=None
L1 L3 L24 L26 L28 L30 L32 L34: library part 0402_IND, "350mA 470nH ±5% 660mΩ 0402  Inductors (SMD) ROHS", INDUCTANCE=470nH
L2 L4 L25 L27 L29 L31 L33 L35: library part 0402_IND, "100mA 180nH ±5% 3.7Ω 0402 Inductors (SMD) ROHS", INDUCTANCE=180nH
L9 L10 L12 L13: library part 0402_IND, "950mA 1.8nH 80mΩ 0402 Inductors (SMD) ROHS", INDUCTANCE=1.8nH
L11 L14: library part 0402_IND, "300mA 12nH ±5% 500mΩ 0402 Inductors (SMD) ROHS", INDUCTANCE=12nH
L15 L16 L18 L19: library part 0402_IND, "1A 1.2nH 70mΩ 0402 Inductors (SMD) ROHS", INDUCTANCE=1.2nH
L17: library part 0402_IND, "Multilayer type RF Inductor 5.6nH ±0.1nH 0.18Ω 650mA 0402", INDUCTANCE=5.6nH
L20 L21 L22 L23 L36 L37 L38 L39 L40 L41 L42 L43 L44 L45 L46 L47: library part 0402_IND, "150mA 150nH ±5% 2.99Ω 0402 Inductors (SMD) ROHS", INDUCTANCE=150nH
R1 R2 R32 R33 R36 R37 R40 R41: library part 0402_RES, "RESISTOR, RES Thick Film, 110Ω, 1%, 0.063W, 100ppm/°C, 0402", RESISTANCE=110
R3 R4 R34 R35 R38 R39 R42 R43: library part 0402_RES, "RESISTOR, RES Thick Film, 20Ω, 1%, 0.063W, 100ppm/°C, 0402", RESISTANCE=20
R5: library part 0402_RES, "62.5mW Thick Film Resistors 50V ±100ppm/℃ ±5% 1kΩ 0402 Chip Resistor - Surface Mount ROHS", RESISTANCE=1k
R6: library part 0402_RES, "DNI, DATASHEET SAYS 51-OHM, SHOULD BE 50-OHM TO GND DUE TO TRACE", RESISTANCE=DNI
R7: library part 0402_RES, "62.5mW Thick Film Resistors 50V ±100ppm/℃ ±1% 360Ω 0402 Chip Resistor - Surface Mount ROHS", RESISTANCE=360
R8: library part 0402_RES, "RES Thick Film, 110Ω, 1%, 0.063W, 100ppm/°C, 0402", RESISTANCE=110
R9 R12 R13 R14 R16 R18: library part 0402_RES, "RES 10K OHM 1% 1/16W 0402", RESISTANCE=10k
R10: library part 0402_RES
R11: library part 0402_RES, "RES Thick Film, 4.7kΩ, 1%, 0.063W, 100ppm/°C, 0402", RESISTANCE=4.7k
R19 R30 R44 R55 R57 R68 R70: library part 0402_RES, "Thick Film Resistors ±100ppm/℃ ±1% 392Ω 0402  Chip Resistor - Surface Mount ROHS", RESISTANCE=392
R20 R27 R45 R52 R58 R65 R71 R78: library part 0402_RES, "62.5mW Thick Film Resistors 50V ±100ppm/℃ ±1% 240Ω 0402 Chip Resistor - Surface Mount ROHS", RESISTANCE=240
R21 R28 R46 R53 R59 R66 R72 R79: library part 0402_RES, "RES Thick Film, 20Ω, 1%, 0.063W, 100ppm/°C, 0402", RESISTANCE=20
R22 R29 R47 R54 R60 R67 R73 R80: library part 0402_RES, "62.5mW Thick Film Resistors 50V ±100ppm/℃ ±1% 82Ω 0402  Chip Resistor - Surface Mount ROHS", RESISTANCE=82Ω
R23 R24 R48 R49 R61 R62 R74 R75: library part 0402_RES, "62.5mW Thick Film Resistors 50V ±100ppm/℃ ±1% 27Ω 0402 Chip Resistor - Surface Mount ROHS", RESISTANCE=27
R25 R26 R50 R51 R63 R64 R76 R77: library part 0402_RES, "RES Thick Film, 150Ω, 1%, 0.063W, 100ppm/°C, 0402", RESISTANCE=150
R31 R56 R69 R82: library part 0402_RES, "63mW Thick Film Resistors 50V ±100ppm/℃ ±1% 100Ω 0402  Chip Resistor - Surface Mount ROHS", RESISTANCE=100
R81: library part 0402_RES, "62.5mW Thick Film Resistors 50V ±1% ±100ppm/℃ 402Ω 0402  Chip Resistor - Surface Mount ROHS", RESISTANCE=392
R83 R84 R85 R86: library part 0402_RES, "62.5mW Thick Film Resistors 50V ±100ppm/℃ ±5% 50Ω 0402 Chip Resistor - Surface Mount ROHS", RESISTANCE=50
T1 T2 T3 T4 T5: "SMD,3.8x3.8mm RF Misc ICs and Modules ROHS"
U1: "2 4Ω SPDT(SPDT) MSOP-10  Analog Switches, Multiplexers ROHS", Manufacturer_Name="Analog Devices"
U2: "10MHz SPI QFN-28-EP(6x6) I/O Expanders ROHS", Manufacturer_Name=Microchip, Manufacturer_Part_Number=MCP23S17T-E/ML
U3: "4.4GHz LFCSP-32(5x5) Clock Generators, PLLs, Frequency Synthesizers ROHS", Manufacturer_Name="Analog Devices"
U4: "30MHz~1.4GHz 9.9dB 5.4dB QFN-24-EP(4x4) RF Modulators and Demodulators ROHS", Manufacturer_Name="Analog Devices"
U5 U7: "Qorvo QPL7442TR7", Manufacturer_Name=Qorvo
U6: "400MHz~4GHz 12.7dB 2.4dB QFN-24-EP(4x4)  RF Modulators and Demodulators ROHS", Manufacturer_Name="Analog Devices"
U8 U11 U12 U13: "QFN-10(2x3)  Differential Amplifiers ROHS", Manufacturer_Name="Analog Devices"
U9: "800mA 68dB@(1MHz) Fixed 3.3V Positive electrode 16V LFCSP-8-EP(3x3) Voltage Regulators - Linear, Low Drop Out (LDO) Regulators ROHS", Manufacturer_Name="Analog Devices"
U10 U14 U15 U16: "70dB@(100Hz) 150mA Fixed 900mV Positive electrode 6.5V WSON-6(1.5x1.5)  Voltage Regulators - Linear, Low Drop Out (LDO) Regulators ROHS", Mfr_Name="Texas Instruments"

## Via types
v1: diameter 0.35, hole 0.25, Top Layer (RF) to Bottom Layer (RF), 474 vias
v2: diameter 0.75, hole 0.5, Top Layer (RF) to Bottom Layer (RF), 365 vias
v3: diameter 0.254, hole 0.254, Top Layer (RF) to Bottom Layer (RF), tented bottom, 15 vias
v4: diameter 0.3, hole 0.3, Top Layer (RF) to Bottom Layer (RF), 14 vias
v5: diameter 0.254, hole 0.254, Top Layer (RF) to Bottom Layer (RF), tented top, 9 vias
v6: diameter 0.254, hole 0.254, Top Layer (RF) to Bottom Layer (RF), 4 vias
v7: diameter 0.5, hole 0.25, Top Layer (RF) to Bottom Layer (RF), 4 vias
v8: diameter 0.254/0.254/0.254/0.254/0.254/0.254 (per signal layer), hole 0.254, Top Layer (RF) to Bottom Layer (RF), tented top, 2 vias

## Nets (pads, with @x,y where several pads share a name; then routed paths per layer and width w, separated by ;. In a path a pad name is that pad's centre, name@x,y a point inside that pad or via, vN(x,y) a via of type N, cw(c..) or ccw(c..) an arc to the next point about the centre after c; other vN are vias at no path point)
"0.9V REG OUT_1": C80.2 C88.1 R25.2 R26.2 R31.2 U10.1 | length 16.7
  Top Layer (RF) w0.152: R31.2@98.02,23.187 v1(98.02,24.961)
  Top Layer (RF) w0.156: C80.2@100.344,21.614 C80.2@100.319,21.589 100.299,21.569 C88.1@102.028,21.569
  Top Layer (RF) w0.2: v4(99.316,21.569) C80.2@100.299,21.569 ; C88.1@102.073,21.614 U10.1@103.734,21.614
  Int3 (Controls) w0.156: v1(98.02,24.961) 97.409,25.571 97.409,26.797 97.912,27.3 98.049,27.3 v1(98.049,27.748) 98.744,27.748 99.316,27.176 v4(99.316,21.569)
